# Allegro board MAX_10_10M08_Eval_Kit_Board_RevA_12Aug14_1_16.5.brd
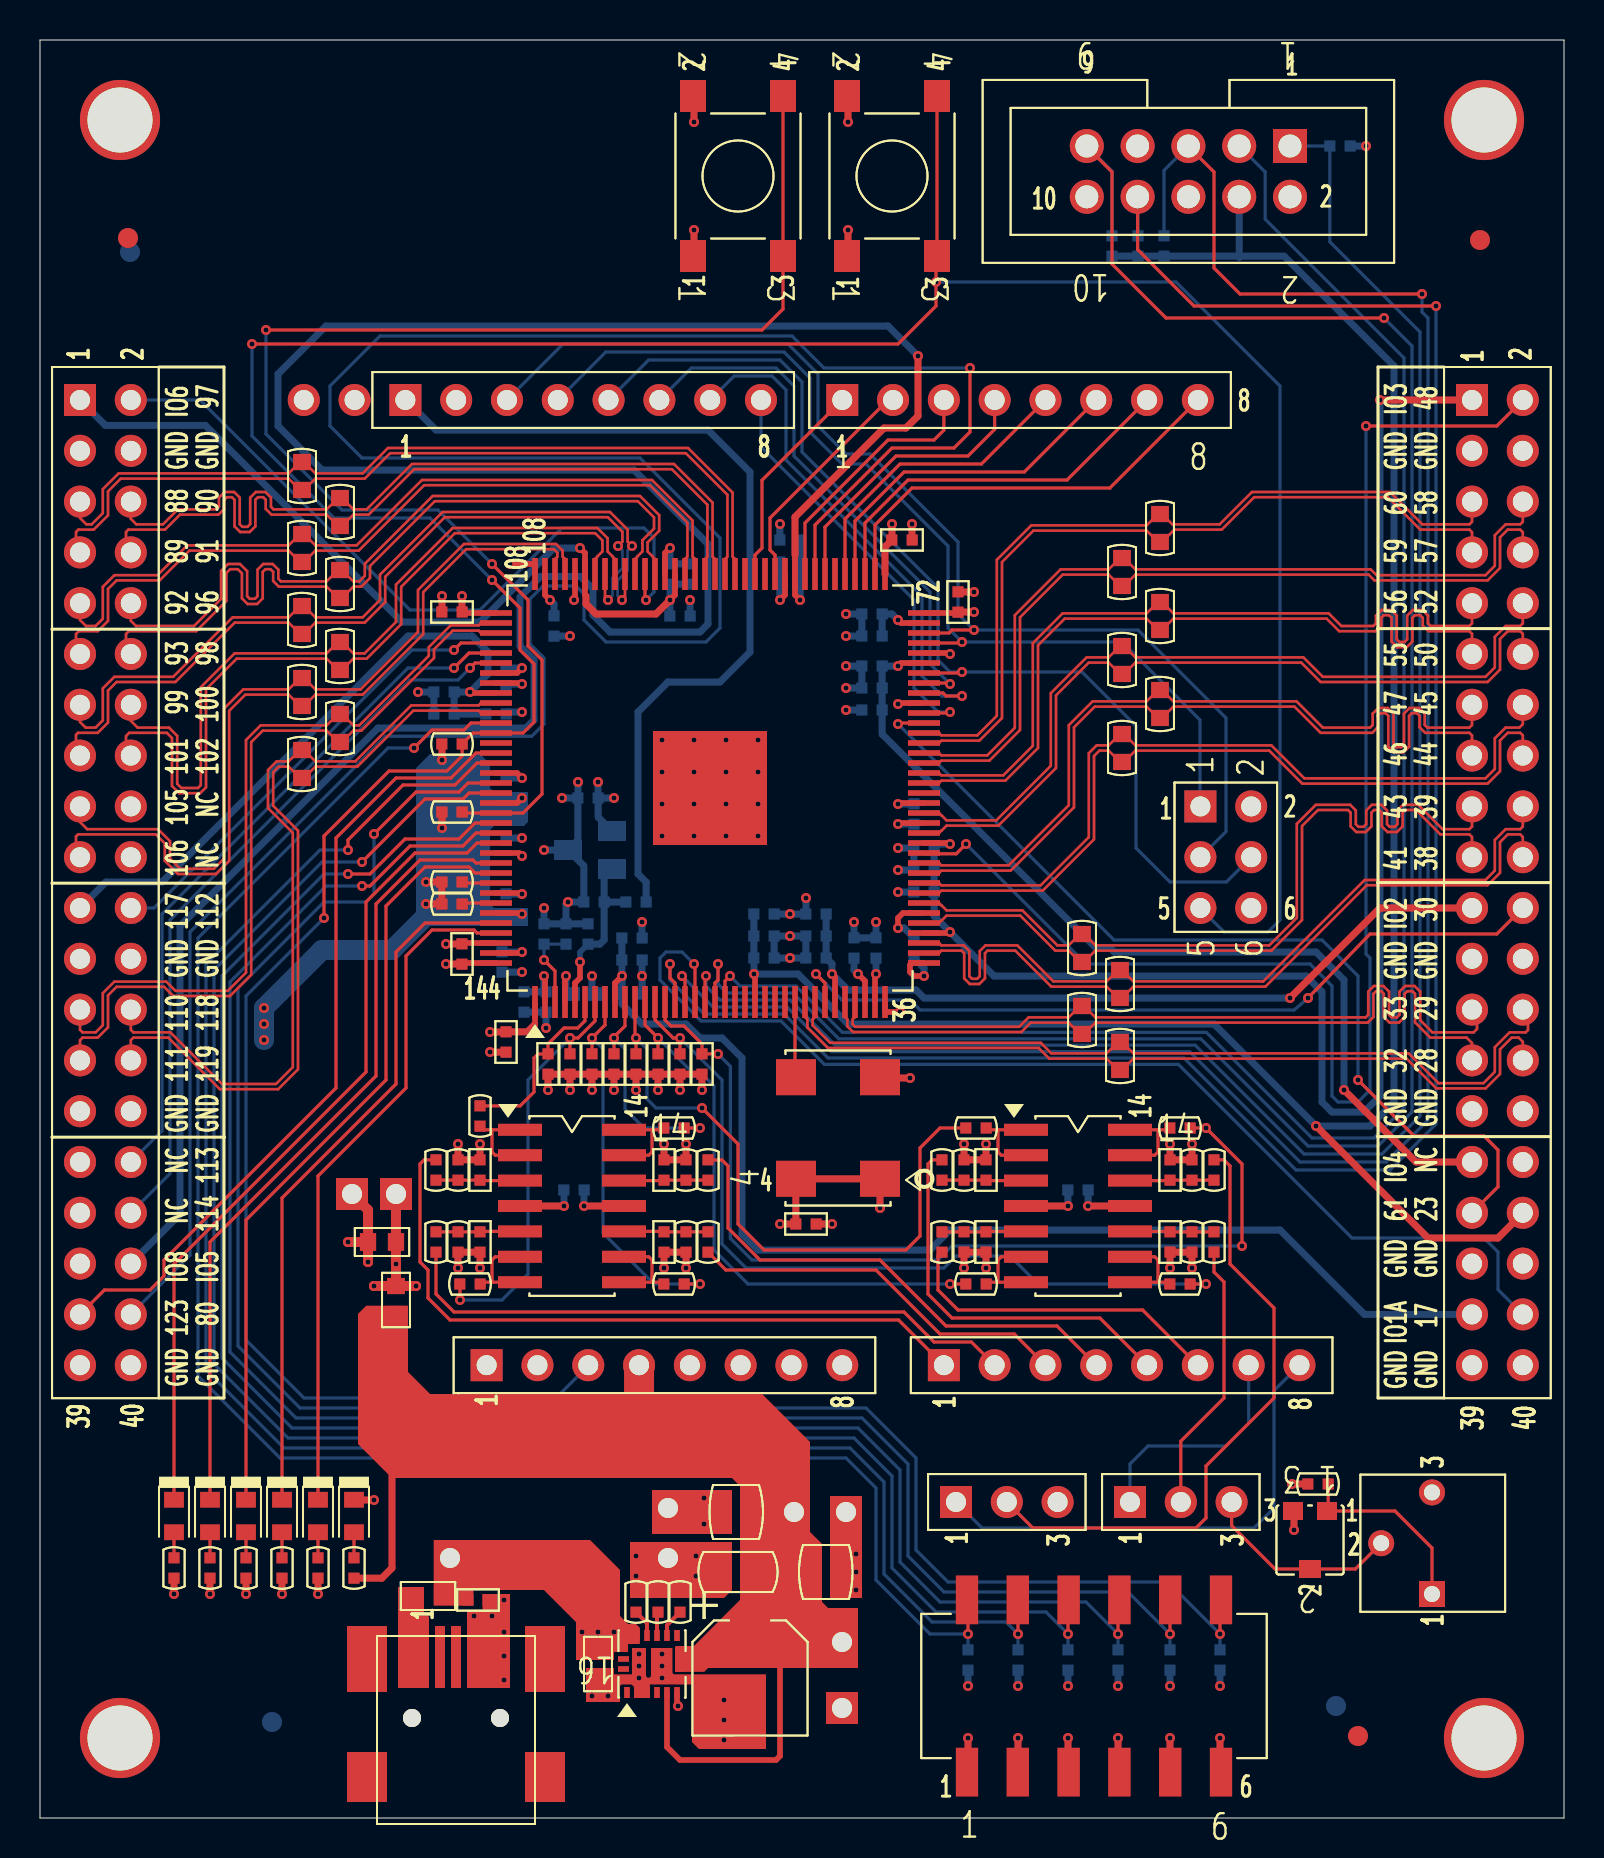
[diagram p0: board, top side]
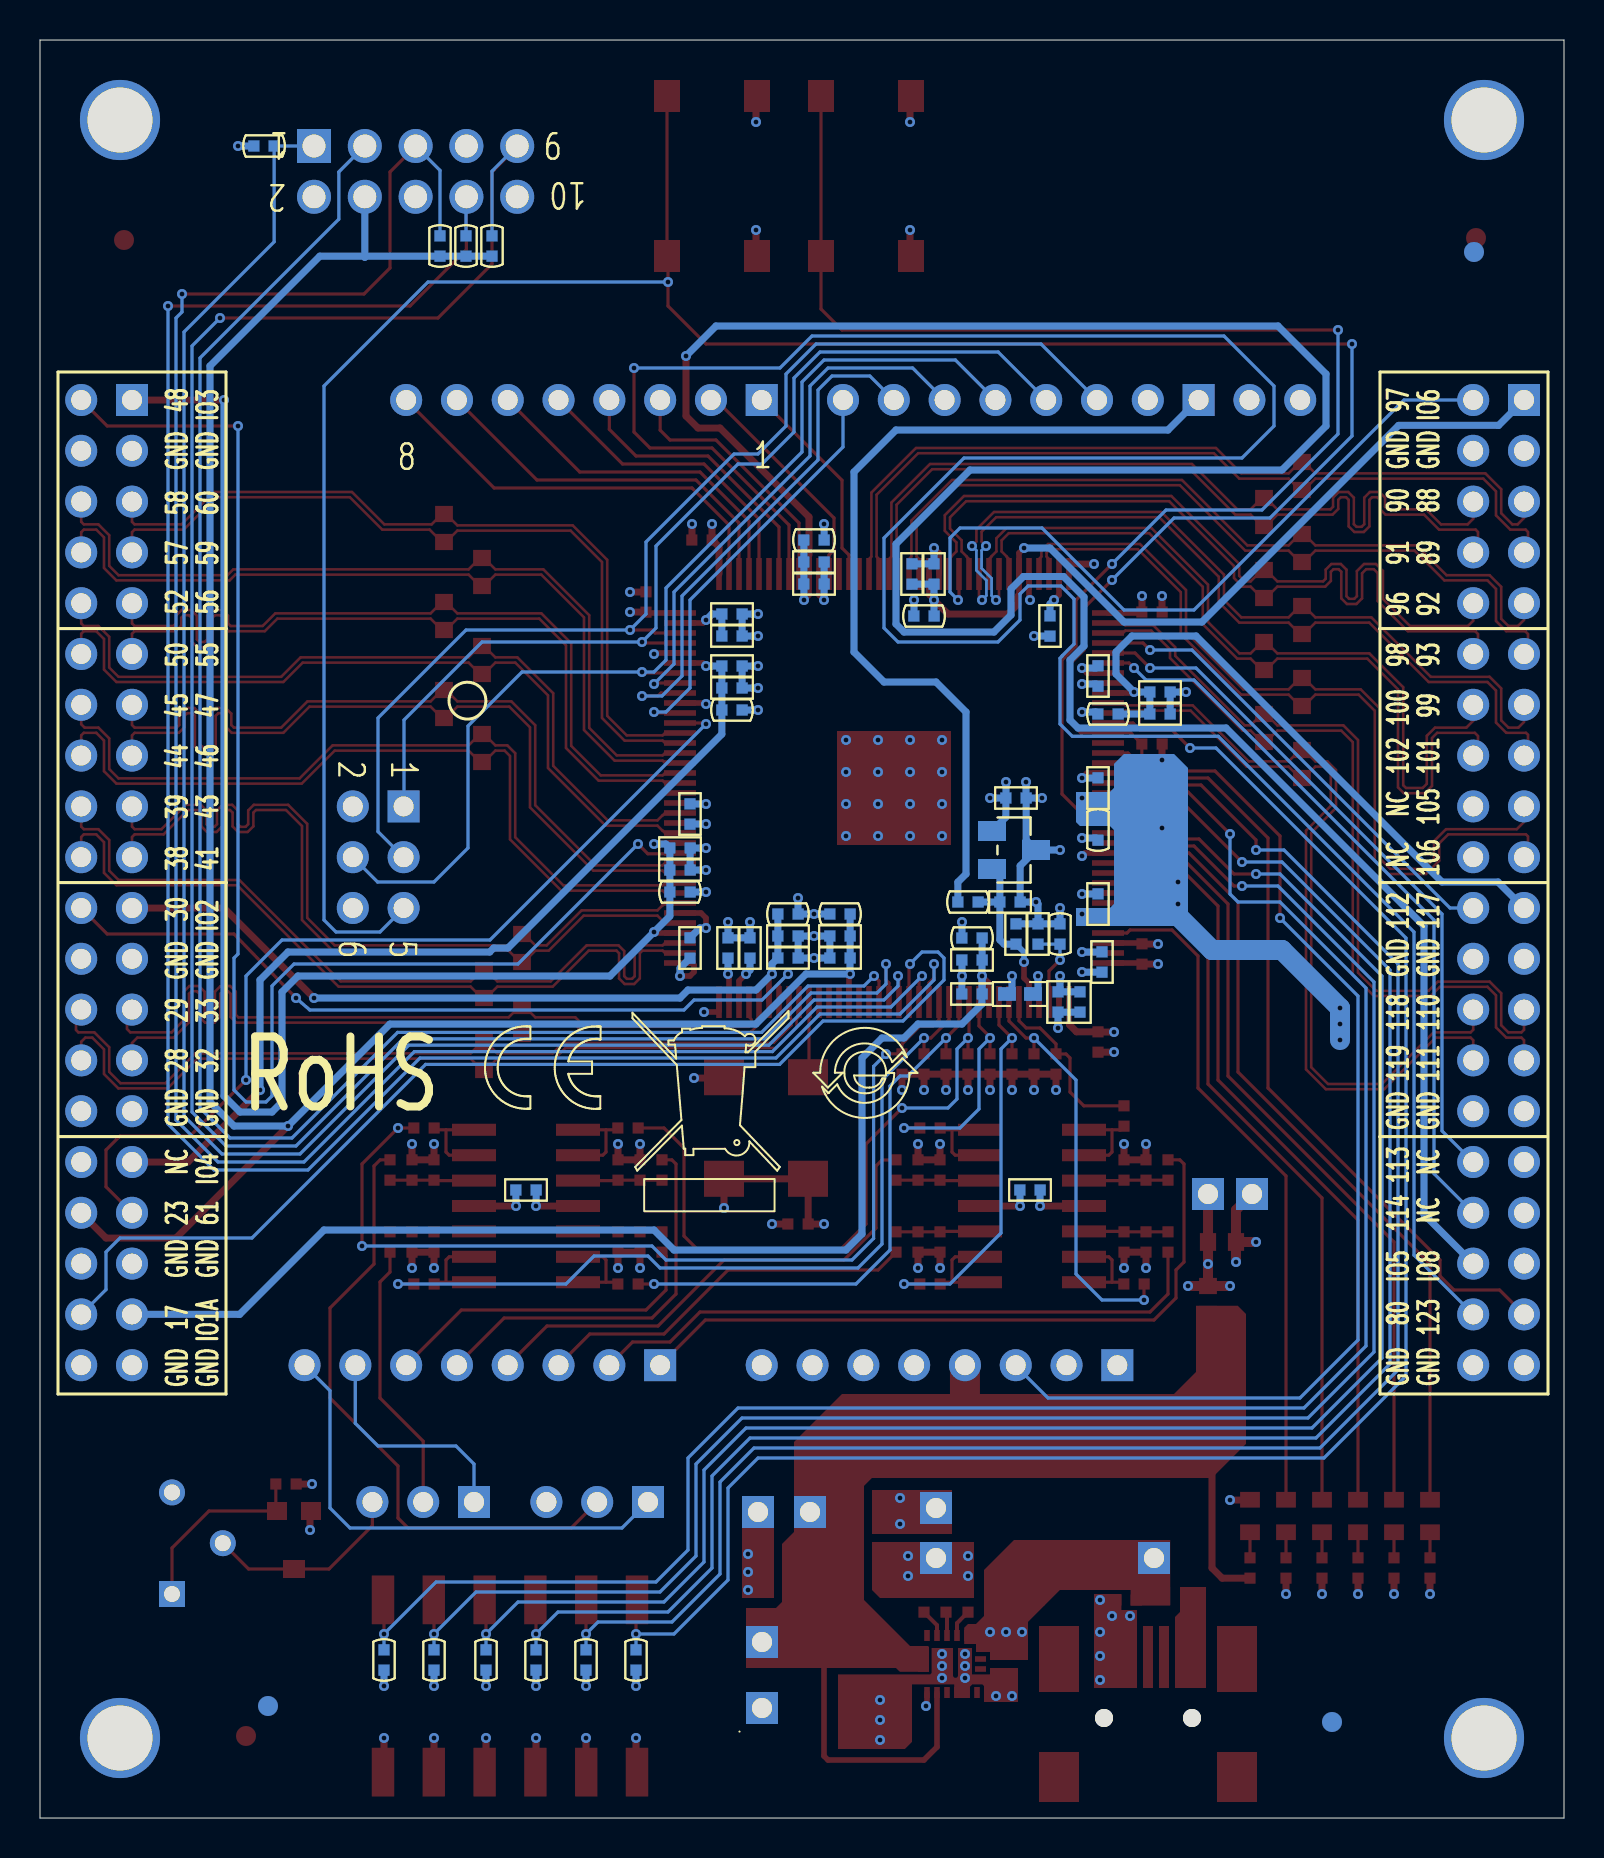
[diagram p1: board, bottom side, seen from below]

Outline 76.2 x 88.9 mm; copper layers: TOP, L2_GND, L3_PWR, BOTTOM. Coordinates in mm from the lower left corner of the outline.
Outline path: 0,88.9 0,0 76.2,0 76.2,88.9 0,88.9

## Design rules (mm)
net group DIFFIO_B1: nets DIFFIO_B1N DIFFIO_B1P
net group DIFFIO_B3: nets DIFFIO_B3N DIFFIO_B3P
net group DIFFIO_B5: nets DIFFIO_B5N DIFFIO_B5P
net group DIFFIO_B7: nets DIFFIO_B7N DIFFIO_B7P
net group DIFFIO_B9: nets DIFFIO_B9N DIFFIO_B9P
net group DIFFIO_B12: nets DIFFIO_B12N DIFFIO_B12P
net group DIFFIO_B14: nets DIFFIO_B14N DIFFIO_B14P
net group DIFFIO_B16: nets DIFFIO_B16N DIFFIO_B16P
net group DIFFIO_R18: nets DIFFIO_R18N DIFFIO_R18P
net group DIFFIO_R27: nets DIFFIO_R27N DIFFIO_R27P
net group DIFFIO_R28: nets DIFFIO_R28N DIFFIO_R28P
net group DIFFIO_R33: nets DIFFIO_R33N DIFFIO_R33P
net group DIFFIO_T1: nets DIFFIO_T1N DIFFIO_T1P
net group DIFFIO_T10: nets DIFFIO_T10N DIFFIO_T10P
net group DP1: nets DIFFIO_L20N/CLK1N DIFFIO_L20P/CLK1P
net group DP2: nets DIFFIO_L27N/PLL_CLKOUTN DIFFIO_L27P/PLL_CLKOUTP
net group DP3: nets DIFFIO_R14N/CLK2N DIFFIO_R14P/CLK2P
net group DP4: nets DIFFIO_R16N/CLK3N DIFFIO_R16P/CLK3P
net group DP5: nets DIFFIO_R26N/DPCLK2 DIFFIO_R26P/DPCLK3

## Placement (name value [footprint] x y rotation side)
C1  4.7uF  [CC0603]  27.9 7.7 270 top
C2  0.1uF  [CC0402]  21.9 10.9 180 top
C3  47uF/16V  [CAP_5P5_5P5_5P5]  35.5 7 180 top
C4  0.1uF  [CC0402]  25.3 40.8 90 bottom
C5  0.1uF  [CC0402]  40.7 43.5 270 bottom
C6  0.1uF  [CC0402]  25.7 59.6 90 bottom
C7  0.1uF  [CC0402]  41.8 43.5 270 bottom
C8  0.1uF  [CC0402]  43.7 43.5 270 bottom
C9  0.1uF  [CC0402]  21.1 43.2 270 top
C10  0.1uF  [CC0402]  23.3 57.1 90 bottom
C11  1uF  [CC0402]  43.1 63.9 180 top
C12  1uF  [CC0402]  27.4 44.2 270 bottom
C13  0.1uF  [CC0402]  23.3 38.8 90 top
C14  0.1uF  [CC0402]  20.6 60.3 0 top
C15  0.1uF  [CC0402]  45.9 60.8 270 top
C16  0.1uF  [CC0402]  43.7 50.2 270 bottom
C17  0.1uF  [CC0402]  29.6 41.2 180 bottom
C18  1uF  [CC0402]  29.6 42.9 180 bottom
C19  1nF  [CC0402]  22 28.8 270 top
C20  1nF  [CC0402]  31.2 32.4 90 top
C21  1nF  [CC0402]  31.2 28.8 270 top
C22  1nF  [CC0402]  22 32.4 90 top
C23  1nF  [CC0402]  47.3 28.8 270 top
C24  1nF  [CC0402]  56.5 32.4 90 top
C25  1nF  [CC0402]  47.3 32.4 90 top
C26  1nF  [CC0402]  56.5 28.8 270 top
C27  0.1uF  [CC0402]  41.6 57.6 0 bottom
C28  1uF  [CC0402]  41.6 56.5 0 bottom
C29  0.1uF  [CC0402]  37.5 61.7 0 bottom
C30  1uF  [CC0402]  37.5 62.8 0 bottom
C31  0.1uF  [CC0402]  38.8 43 0 bottom
C32  1uF  [CC0402]  38.8 44.1 0 bottom
C33  0.1uF  [CC0402]  44.2 48.5 0 bottom
C34  1uF  [CC0402]  44.2 47.4 0 bottom
C35  0.1uF  [CC0402]  38.3 29.7 180 top
C36  0.1uF  [CC0402]  31.5 62.2 270 bottom
C37  1uF  [CC0402]  32.6 62.2 270 bottom
C38  0.1uF  [CC0402]  20.2 56.3 0 bottom
C39  1uF  [CC0402]  20.2 55.2 0 bottom
C40  0.1uF  [CC0402]  23.3 45.7 270 bottom
C41  1uF  [CC0402]  23.3 51.5 270 bottom
C42  0.1uF  [CC0402]  36.2 43 180 bottom
C43  1uF  [CC0402]  36.2 44.1 180 bottom
C44  1uF  [CC0402]  24.2 40.8 90 bottom
C45  1uF  [CC0402]  41.6 59.1 0 bottom
C46  0.1uF  [CC0402]  26.3 44.2 270 bottom
C47  0.1uF  [CC0402]  27.4 51 0 bottom
C48  0.1uF  [CC0402]  23.1 42.8 90 bottom
C49  0.1uF  [CC0402]  41.6 60.2 0 bottom
C50  10uF  [CC0603]  17.1 28.8 180 top
C51  0.1uF  [CC0402]  26.7 31.4 180 bottom
C52  0.1uF  [CC0402]  51.9 31.4 180 bottom
C53  1nF  [CC0402]  25.4 37.7 270 top
C54  1nF  [CC0402]  26.5 37.7 270 top
C55  1nF  [CC0402]  27.6 37.7 270 top
C56  1nF  [CC0402]  28.7 37.7 270 top
C57  1nF  [CC0402]  29.8 37.7 270 top
C58  1nF  [CC0402]  30.9 37.7 270 top
C59  1nF  [CC0402]  32 37.7 270 top
C60  1nF  [CC0402]  33.1 37.7 270 top
C61  1uF  [CC0402]  27.7 45.8 0 bottom
D1  Red  [LED_0603]  6.7 15.1 90 top
D2  Red  [LED_0603]  8.5 15.1 90 top
D3  Red  [LED_0603]  10.3 15.1 90 top
D4  Red  [LED_0603]  12.1 15.1 90 top
D5  Red  [LED_0603]  13.9 15.1 90 top
D6  Green  [LED_0603]  15.7 15.1 90 top
J1  -  [SKT_MINIUSB_B_RA]  20.8 5 0 top
J2  PPTC081LFBN-RC  [SKT_SULLINS_PPTC_1X8_100]  22.33 22.64 0 top
J3  PPTC081LFBN-RC  [SKT_SULLINS_PPTC_1X8_100_ALT1]  18.27 70.9 0 top
J4  PPTC081LFBN-RC  [SKT_SULLINS_PPTC_1X8_100]  45.19 22.64 0 top
J5  PPTC081LFBN-RC  [SKT_SULLINS_PPTC_1X8_100]  40.11 70.9 0 top
J6  HEADER 3  [HDR_3M_961_1X3_100]  45.8 15.8 0 top
J7  HEADER 3  [HDR_3M_961_1X3_100]  54.5 15.8 0 top
J8  Header2x20  [SKT_SULLINS_PPPC_2X20_100]  71.6 70.9 270 top
J9  Header2x20  [SKT_SULLINS_PPPC_2X20_100]  2 70.9 270 top
J10  70246-1004  [HDR_MOLEX_70246_2X5_100]  62.5 83.6 180 top
J11  87227-3  [HDR_TE_87227_2X3_100]  58.02 50.58 0 top
L1  600ohm 500mA  [FB0603]  19.4 11.1 180 top
L2  600ohm 500mA  [FB0603]  17.8 25.9 90 top
L3  Ferrite Bead  [FB0402]  27.2 41.2 180 bottom
NOREF  -  [unnamed]  65.9 4.1 0 top
NOREF#2  -  [#2]  -5 -152.4 90 top
NOREF#3  -  [unnamed]  72 78.9 0 top
NOREF#4  -  [unnamed]  72.2 4 0 top
NOREF#5  -  [unnamed]  4 4 0 top
NOREF#6  -  [#2]  139.19 -79.15 0 top
NOREF#7  -  [#2]  -5 -152.5 0 top
NOREF#8  -  [#2]  0 0 90 top
NOREF#9  -  [unnamed]  4.4 79 0 top
NOREF#10  -  [#2]  231.1 -145.9 0 top
NOREF#11  -  [unnamed]  4 84.9 0 top
NOREF#12  -  [unnamed]  72.2 84.9 0 top
NOREF#13  -  [#2]  0 88.9 0 top
NOREF#14  -  [unnamed]  4.5 78.3 180 bottom
NOREF#15  -  [unnamed]  64.8 5.6 180 bottom
NOREF#16  -  [#2]  234.19 -137.57 180 bottom
NOREF#17  -  [unnamed]  11.6 4.8 180 bottom
R1  0.1  [CR0805W]  39.3 12.3 0 top
R2  1K  [CR0402]  15.7 12.5 270 top
R3  100  [CR0805]  34.9 12.3 0 top
R4  0.1  [CR0805W]  34.8 15.3 180 top
R6  0  [CR0402]  29.6 44 0 bottom
R7  316  [CR0402]  33.4 28.8 270 top
R8  316  [CR0402]  19.8 28.8 270 top
R9  316  [CR0402]  33.4 32.4 90 top
R10  316  [CR0402]  19.8 32.4 90 top
R15  1K  [CR0402]  63.9 16.7 180 top
R16  10K  [RV_MURATA_PVZ3A]  63.5 13.9 180 top
R17  316  [CR0402]  58.7 32.4 90 top
R18  316  [CR0402]  45.1 28.8 270 top
R19  316  [CR0402]  58.7 28.8 270 top
R20  316  [CR0402]  45.1 32.4 90 top
R25  0  [CR0402]  41.6 55.4 180 bottom
R26  0  [CR0402]  37.5 63.9 180 bottom
R27  0  [CR0402]  38.8 45.2 180 bottom
R29  100  [CR0603]  56 55.7 90 top
R30  100  [CR0603]  54 41.7 90 top
R31  100  [CR0603]  54 38.1 90 top
R32  100  [CR0603]  54.1 57.9 90 top
R33  100  [CR0603]  52.1 43.5 90 top
R34  100  [CR0603]  52.1 39.9 90 top
R35  100  [CR0603]  56 60.1 90 top
R36  100  [CR0603]  54.1 53.5 90 top
R37  100  [CR0603]  54.1 62.3 90 top
R38  0  [CR0402]  44.2 46.3 180 bottom
R39  100  [CR0603]  56 64.5 90 top
R40  0  [CR0402]  32 60.1 0 bottom
R41  100  [CR0603]  13.1 67.1 270 top
R42  100  [CR0603]  15 54.5 270 top
R43  100  [CR0603]  15 65.3 270 top
R44  100  [CR0603]  13.1 52.7 270 top
R45  100  [CR0603]  13.1 63.5 270 top
R46  100  [CR0603]  15 61.7 270 top
R47  0  [CR0402]  22.8 55.2 0 bottom
R48  100  [CR0603]  13.1 59.9 270 top
R49  100  [CR0603]  15 58.1 270 top
R50  100  [CR0603]  13.1 56.3 270 top
R51  1K  [CR0402]  20.6 46.8 180 top
R52  1K  [CR0402]  20.6 45.7 180 top
R53  1K  [CR0402]  20.6 50.3 180 top
R54  10K  [CR0402]  53.6 78.6 270 bottom
R55  10K  [CR0402]  56.2 78.6 270 bottom
R56  10K  [CR0402]  54.9 78.6 270 bottom
R57  1K  [CR0402]  6.7 12.5 90 top
R58  1K  [CR0402]  8.5 12.5 90 top
R59  1K  [CR0402]  10.3 12.5 90 top
R60  1K  [CR0402]  12.1 12.5 90 top
R61  1K  [CR0402]  13.9 12.5 90 top
R62  1K  [CR0402]  65 83.6 180 bottom
R63  0  [CR0402]  23.3 49.4 270 bottom
R64  1K  [CR0402]  59 7.9 90 bottom
R65  1K  [CR0402]  56.5 7.9 90 bottom
R66  1K  [CR0402]  53.9 7.9 90 bottom
R67  1K  [CR0402]  51.4 7.9 90 bottom
R68  1K  [CR0402]  48.9 7.9 90 bottom
R69  1K  [CR0402]  46.4 7.9 90 bottom
R70  0  [CR0402]  36.2 45.2 0 bottom
R72  1K  [CR0402]  20.6 53.7 0 top
R73  0  [CR0402]  25.2 44.2 270 bottom
R74  0  [CR0402]  29.8 45.8 180 bottom
R75  0  [CR0402]  29.8 10.8 270 top
R76  0  [CR0402]  30.9 10.8 270 top
R77  0  [CR0402]  32 10.8 270 top
R78  316  [CR0402]  20.9 32.4 90 top
R79  316  [CR0402]  20.9 28.8 270 top
R80  316  [CR0402]  32.3 28.8 270 top
R81  316  [CR0402]  32.3 32.4 90 top
R82  316  [CR0402]  46.2 32.4 90 top
R83  316  [CR0402]  46.2 28.8 270 top
R84  316  [CR0402]  57.6 28.8 270 top
R85  316  [CR0402]  57.6 32.4 90 top
R86  100  [CR0402]  22 35.1 90 top
R87  100  [CR0402]  21.5 26.7 180 top
R88  100  [CR0402]  31.7 26.7 0 top
R89  100  [CR0402]  31.7 34.5 0 top
R90  100  [CR0402]  46.8 34.5 0 top
R91  100  [CR0402]  46.8 26.7 0 top
R92  100  [CR0402]  57 26.7 180 top
R93  100  [CR0402]  57 34.5 180 top
R94  10K  [RV_BOURNS_3362P]  69.6 11.2 90 top
SW1  PTS645SM43SMTR92 LFS  [SW_SP_ST_CK_PTS645_SM]  42.6 82.1 270 top
SW2  PTS645SM43SMTR92 LFS  [SW_SP_ST_CK_PTS645_SM]  34.9 82.1 270 top
SW3  219-6LPST  [SW_SP_ST_CTS_219_GW]  52.7 6.6 0 top
TP1  -  [TP_S_40_63]  20.5 13 0 top
TP2  -  [TP_S_40_63]  37.7 15.3 0 top
TP3  -  [TP_S_40_63]  40.3 15.3 0 top
TP4  -  [TP_S_40_63]  40.1 8.8 0 top
TP5  -  [TP_S_40_63]  31.4 15.5 0 top
TP6  -  [TP_S_40_63]  17.8 31.2 90 top
TP7  -  [TP_S_40_63]  15.6 31.2 90 top
TP8  -  [TP_S_40_63]  40.1 5.5 0 top
TP9  -  [TP_S_40_63]  31.4 13 0 top
U1  EP5388QI  [QFN16_0P5_3P0X3P0_H1P1]  30.6 7.7 90 top
U2  MAX 10M08  [TQFP144_0P5_22P2X22P2_H1P6_EP]  33.5 51.5 90 top
U3  LM2902DR2  [SO14_50_244]  26.6 30.6 0 top
U4  LM2902DR2  [SO14_50_244]  51.9 30.6 0 top
U5  MCP1525  [SOT23_3P]  27.5 48.4 270 bottom
X1  CB3LV-3C-50M0000  [OSC_4P_CB3LV]  39.9 34.5 90 top

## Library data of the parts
C1 = CAP NP
C2 C4-C49 C51-C61 = C
C3 = EEE-1CA470WR
C50 = LMK107BJ106MALTD
D1-D5 = LED_0603_Red
D6 = LED_LTST-C190KGKT
J1 = skt_miniusb_b_ra
J2 = Arduino UNO Connector - 1_1
J3 = Arduino UNO Connector - 3_1
J4 = Arduino UNO Connector - 2_1
J5 = Arduino UNO Connector - 4_1
J6 = HEADER 3_1
J7 = HEADER 3_0
J8 J9 = header2x20_0
J10 = header2x5_ftsh
J11 = hdr2x3_87227
L1 L2 = FB0603
L3 = BEAD
R1 R4 = ERJ-3RSFR10V
R2 R3 R6-R10 R15 R17-R20 R25-R27 R38 R40 R47 R51-R56 R63 R70 R73-R85 = R
R16 = PVZ3A103C01R00
R29-R37 R39 R41-R46 R48-R50 = 100R_0603
R57-R62 R64-R69 R72 = 1k_0402
R86-R93 = RC0402FR-07100RL
R94 = 3362P-1-103TLF
SW1 SW2 = EVQP0_1
SW3 = SW DIP-6/SM_0
TP1-TP9 = TP_S_40_0
U1 = EP5388QI_0
U2 = MAX 10M08_27
U3 U4 = LM2902DR2_0
U5 = MCP1525
X1 = crystal_50MhZ

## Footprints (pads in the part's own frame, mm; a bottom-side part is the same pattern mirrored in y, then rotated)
CAP_5P5_5P5_5P5
  rect 1.6x2.8 smd: 1(0,-2.15) 2(0,2.15)
CC0402
  rect 0.559x0.559 smd: 1(-0.508,0) 2(0.508,0)
CC0603
  rect 0.813x0.889 smd: 1(-0.699,0) 2(0.699,0)
CR0402
  rect 0.559x0.559 smd: 1(-0.508,0) 2(0.508,0)
CR0603
  rect 0.813x0.889 smd: 1(-0.699,0) 2(0.699,0)
CR0805
  rect 1.295x1.499 smd: 1(-0.95,0) 2(0.95,0)
CR0805W
  rect 0.74x2.2 smd: 1(-0.62,0) 2(0.62,0)
FB0402
  rect 0.889x0.686 smd: 1(-0.65,0) 2(0.65,0)
FB0603
  rect 0.813x0.889 smd: 1(-0.699,0) 2(0.699,0)
HDR_3M_961_1X3_100
  rect 1.6x1.6 hole 1: 1(0,0)
  round 1.6 hole 1: 2(2.54,0) 3(5.08,0)
HDR_MOLEX_70246_2X5_100
  rect 1.7x1.7 hole 1.15: 1(0,0)
  round 1.7 hole 1.15: 2(0,2.54) 3(2.54,0) 4(2.54,2.54) 5(5.08,0) 6(5.08,2.54) 7(7.62,0) 8(7.62,2.54) 9(10.16,0) 10(10.16,2.54)
HDR_TE_87227_2X3_100
  rect 1.6x1.6 hole 1: 1(0,0)
  round 1.6 hole 1: 2(2.54,0) 3(0,-2.54) 4(2.54,-2.54) 5(0,-5.08) 6(2.54,-5.08)
LED_0603
  rect 0.787x0.991 smd: 1(-0.813,0) 2(0.813,0)
OSC_4P_CB3LV
  rect 1.8x2 smd: 1(-2.54,-2.1) 2(2.54,-2.1) 3(2.54,2.1) 4(-2.54,2.1)
QFN16_0P5_3P0X3P0_H1P1
  rect 0.55x0.28 smd: 1(-1.425,1.25) 2(-1.425,0.75) 3(-1.425,0.25) 4(-1.425,-0.25) 5(-1.425,-0.75) 6(-1.425,-1.25) 9(1.425,-1.25) 10(1.425,-0.75) 11(1.425,-0.25) 12(1.425,0.25) 13(1.425,0.75) 14(1.425,1.25)
  rect 0.28x0.55 smd: 7(-0.25,-1.425) 8(0.25,-1.425) 15(0.25,1.425) 16(-0.25,1.425)
RV_BOURNS_3362P
  rect 1.3x1.3 hole 0.8: 1(0,0)
  round 1.3 hole 0.8: 2(2.54,2.54) 3(5.08,0)
RV_MURATA_PVZ3A
  rect 1x0.9 smd: 1(-0.85,-1.45) 3(0.85,-1.45)
  rect 1.1x0.9 smd: 2(0,1.45)
SKT_MINIUSB_B_RA
  rect 2x3.3 smd: (-4.45,2.95) (4.45,2.95)
  rect 2x2.5 smd: (-4.45,-2.95) (4.45,-2.95)
  round 0.9 hole 0.9 unplated: (-2.2,0) (2.2,0)
  rect 0.5x3.1 smd: 1(-1.6,3.05) 2(-0.8,3.05) 3(0,3.05) 4(0.8,3.05) 5(1.6,3.05)
SKT_SULLINS_PPPC_2X20_100
  rect 1.6x1.6 hole 1: 1(0,0)
  round 1.6 hole 1: 2(0,2.54) 3(2.54,0) 4(2.54,2.54) 5(5.08,0) 6(5.08,2.54) 7(7.62,0) 8(7.62,2.54) 9(10.16,0) 10(10.16,2.54) 11(12.7,0) 12(12.7,2.54) 13(15.24,0) 14(15.24,2.54) 15(17.78,0) 16(17.78,2.54) 17(20.32,0) 18(20.32,2.54) 19(22.86,0) 20(22.86,2.54) 21(25.4,0) 22(25.4,2.54) 23(27.94,0) 24(27.94,2.54) 25(30.48,0) 26(30.48,2.54) 27(33.02,0) 28(33.02,2.54) 29(35.56,0) 30(35.56,2.54) 31(38.1,0) 32(38.1,2.54) 33(40.64,0) 34(40.64,2.54) 35(43.18,0) 36(43.18,2.54) 37(45.72,0) 38(45.72,2.54) 39(48.26,0) 40(48.26,2.54)
SKT_SULLINS_PPTC_1X8_100
  rect 1.6x1.6 hole 1: 1(0,0)
  round 1.6 hole 1: 2(2.54,0) 3(5.08,0) 4(7.62,0) 5(10.16,0) 6(12.7,0) 7(15.24,0) 8(17.78,0)
SKT_SULLINS_PPTC_1X8_100_ALT1
  round 1.6 hole 1: (-5.08,0) (-2.54,0) 2(2.54,0) 3(5.08,0) 4(7.62,0) 5(10.16,0) 6(12.7,0) 7(15.24,0) 8(17.78,0)
  rect 1.6x1.6 hole 1: 1(0,0)
SO14_50_244
  rect 2.2x0.6 smd: 1(-2.6,3.81) 2(-2.6,2.54) 3(-2.6,1.27) 4(-2.6,0) 5(-2.6,-1.27) 6(-2.6,-2.54) 7(-2.6,-3.81) 8(2.6,-3.81) 9(2.6,-2.54) 10(2.6,-1.27) 11(2.6,0) 12(2.6,1.27) 13(2.6,2.54) 14(2.6,3.81)
SOT23_3P
  rect 1x1.4 smd: 1(-0.95,-1.1) 2(0.95,-1.1) 3(0,1.1)
SW_SP_ST_CK_PTS645_SM
  rect 1.6x1.3 smd: 1(4,-2.25) 2(-4,-2.25) 3(4,2.25) 4(-4,2.25)
SW_SP_ST_CTS_219_GW
  rect 1.118x2.438 smd: 1(-6.35,-4.305) 2(-3.81,-4.305) 3(-1.27,-4.305) 4(1.27,-4.305) 5(3.81,-4.305) 6(6.35,-4.305) 7(6.35,4.305) 8(3.81,4.305) 9(1.27,4.305) 10(-1.27,4.305) 11(-3.81,4.305) 12(-6.35,4.305)
TP_S_40_63
  rect 1.6x1.6 hole 1: 1(0,0)
TQFP144_0P5_22P2X22P2_H1P6_EP
  rect 1.6x0.28 smd: 1(-10.7,8.75) 2(-10.7,8.25) 3(-10.7,7.75) 4(-10.7,7.25) 5(-10.7,6.75) 6(-10.7,6.25) 7(-10.7,5.75) 8(-10.7,5.25) 9(-10.7,4.75) 10(-10.7,4.25) 11(-10.7,3.75) 12(-10.7,3.25) 13(-10.7,2.75) 14(-10.7,2.25) 15(-10.7,1.75) 16(-10.7,1.25) 17(-10.7,0.75) 18(-10.7,0.25) 19(-10.7,-0.25) 20(-10.7,-0.75) 21(-10.7,-1.25) 22(-10.7,-1.75) 23(-10.7,-2.25) 24(-10.7,-2.75) 25(-10.7,-3.25) 26(-10.7,-3.75) 27(-10.7,-4.25) 28(-10.7,-4.75) 29(-10.7,-5.25) 30(-10.7,-5.75) 31(-10.7,-6.25) 32(-10.7,-6.75) 33(-10.7,-7.25) 34(-10.7,-7.75) 35(-10.7,-8.25) 36(-10.7,-8.75) 73(10.7,-8.75) 74(10.7,-8.25) 75(10.7,-7.75) 76(10.7,-7.25) 77(10.7,-6.75) 78(10.7,-6.25) 79(10.7,-5.75) 80(10.7,-5.25) 81(10.7,-4.75) 82(10.7,-4.25) 83(10.7,-3.75) 84(10.7,-3.25) 85(10.7,-2.75) 86(10.7,-2.25) 87(10.7,-1.75) 88(10.7,-1.25) 89(10.7,-0.75) 90(10.7,-0.25) 91(10.7,0.25) 92(10.7,0.75) 93(10.7,1.25) 94(10.7,1.75) 95(10.7,2.25) 96(10.7,2.75) 97(10.7,3.25) 98(10.7,3.75) 99(10.7,4.25) 100(10.7,4.75) 101(10.7,5.25) 102(10.7,5.75) 103(10.7,6.25) 104(10.7,6.75) 105(10.7,7.25) 106(10.7,7.75) 107(10.7,8.25) 108(10.7,8.75)
  rect 0.28x1.6 smd: 37(-8.75,-10.7) 38(-8.25,-10.7) 39(-7.75,-10.7) 40(-7.25,-10.7) 41(-6.75,-10.7) 42(-6.25,-10.7) 43(-5.75,-10.7) 44(-5.25,-10.7) 45(-4.75,-10.7) 46(-4.25,-10.7) 47(-3.75,-10.7) 48(-3.25,-10.7) 49(-2.75,-10.7) 50(-2.25,-10.7) 51(-1.75,-10.7) 52(-1.25,-10.7) 53(-0.75,-10.7) 54(-0.25,-10.7) 55(0.25,-10.7) 56(0.75,-10.7) 57(1.25,-10.7) 58(1.75,-10.7) 59(2.25,-10.7) 60(2.75,-10.7) 61(3.25,-10.7) 62(3.75,-10.7) 63(4.25,-10.7) 64(4.75,-10.7) 65(5.25,-10.7) 66(5.75,-10.7) 67(6.25,-10.7) 68(6.75,-10.7) 69(7.25,-10.7) 70(7.75,-10.7) 71(8.25,-10.7) 72(8.75,-10.7) 109(8.75,10.7) 110(8.25,10.7) 111(7.75,10.7) 112(7.25,10.7) 113(6.75,10.7) 114(6.25,10.7) 115(5.75,10.7) 116(5.25,10.7) 117(4.75,10.7) 118(4.25,10.7) 119(3.75,10.7) 120(3.25,10.7) 121(2.75,10.7) 122(2.25,10.7) 123(1.75,10.7) 124(1.25,10.7) 125(0.75,10.7) 126(0.25,10.7) 127(-0.25,10.7) 128(-0.75,10.7) 129(-1.25,10.7) 130(-1.75,10.7) 131(-2.25,10.7) 132(-2.75,10.7) 133(-3.25,10.7) 134(-3.75,10.7) 135(-4.25,10.7) 136(-4.75,10.7) 137(-5.25,10.7) 138(-5.75,10.7) 139(-6.25,10.7) 140(-6.75,10.7) 141(-7.25,10.7) 142(-7.75,10.7) 143(-8.25,10.7) 144(-8.75,10.7)
  rect 5.7x5.7 smd: 145(0,0)
unnamed
  round 1 smd: (0,0)

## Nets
3.3V: C3.1 J2.4(VCC3P3) L2.1 R1.1 R2.2 R3.2 R4.1 TP2.1(TP) TP4.1(TP) U1.5(VSENSE) U1.7(VOUT1) U1.8(VOUT2)
AGND: C4.1 C5.1 C6.1 C7.1 C12.1 C17.1 C18.1 C19.2 C20.2 C21.2 C22.2 C23.2 C24.2 C25.2 C26.2 C44.1 C45.1 C46.1 C47.1 C48.1 C49.1 C50.2 C51.1 C52.1 C53.2 C54.2 C55.2 C56.2 C57.2 C58.2 C59.2 C60.2 C61.1 J3.2(GND) J6.3 L3.1 R16.3 R73.1 R78.2 R79.2 R80.2 R81.2 R82.2 R83.2 R84.2 R85.2 R94.3 TP7.1(TP) U3.11(GND) U4.11(GND) U5.3(VSS)
DGND: C1.2 C2.1 C3.2 C8.1 C9.1 C10.1 C11.1 C13.1 C14.1 C15.1 C16.1 C27.1 C28.1 C29.1 C30.1 C31.1 C32.1 C33.1 C34.1 C35.1 C36.1 C37.1 C38.1 C39.1 C40.1 C41.1 C42.1 C43.1 D6.2(CATHODE) J1.4(ID) J1.5(GND) J2.6(GND1) J2.7(GND2) J8.3 J8.4 J8.23 J8.24 J8.29 J8.30 J8.35 J8.36 J8.39 J8.40 J9.3 J9.4 J9.23 J9.24 J9.29 J9.30 J9.39 J9.40 J10.2 J10.10 J11.6 R3.1 R62.1 R75.1 R76.1 R77.1 SW1.1(A1) SW1.2(A2) SW2.1(A1) SW2.2(A2) SW3.1(A1) SW3.2(A2) SW3.3(A3) SW3.4(A4) SW3.5(A5) SW3.6(A6) TP8.1(TP) TP9.1(TP) U1.2(PGND1) U1.3(PGND2) U1.6(AGND) U2.42(GND1) U2.53(GND2) U2.63(GND3) U2.68(GND4) U2.83(GND5) U2.95(GND6) U2.104(GND7) U2.116(GND8) U2.125(GND9) U2.133(GND10) U2.137(GND11) U2.142(GND12) U2.145(PAD) X1.2(GND)
VBUS_5V: C1.1 C2.2 J2.5(VCC5) J11.2 L1.1 TP1.1(TP) U1.13(ENABLE) U1.14(VIN)
VCC_CORE: C8.2 C9.2 C10.2 C11.2 C13.2 C14.2 C15.2 C16.2 C35.2 R1.2 TP3.1(TP) U2.1(VCC_ONE10) U2.36(VCC_ONE5) U2.37(VCC_ONE4) U2.51(VCC_ONE3) U2.72(VCC_ONE2) U2.73(VCC_ONE1) U2.108(VCC_ONE9) U2.109(VCC_ONE8) U2.115(VCC_ONE7) U2.144(VCC_ONE6) X1.1(EN) X1.4(VCC)
VCC_IO: J2.2(IOREF) R4.2 R25.2 R26.2 R27.2 R38.2 R40.2 R47.2 R63.2 R70.2 TP5.1(TP)
VCC_IO1A: C17.2 C18.2 J8.37 R6.1 U2.9(VCCIO1A)
VCC_IO1B: C42.2 C43.2 J8.34 J10.4 R54.2 R55.2 R56.2 R70.1 U2.23(VCCIO1B)
VCC_IO2: C31.2 C32.2 J8.21 R27.1 U2.31(VCCIO2)
VCC_IO3: C33.2 C34.2 J8.1 R38.1 U2.40(VCCIO3_1) U2.49(VCCIO3_2)
VCC_IO4: C27.2 C28.2 J8.31 R25.1 U2.67(VCCIO4)
VCC_IO5: C29.2 C30.2 J9.36 R26.1 U2.82(VCCIO5)
VCC_IO6: C36.2 C37.2 J9.1 R40.1 U2.94(VCCIO6_1) U2.103(VCCIO6_2)
VCC_IO7: C38.2 C39.2 J9.21 R47.1 U2.117(VCCIO7)
VCC_IO8: C40.2 C41.2 J9.35 R51.2 R52.2 R53.2 R57.1 R58.1 R59.1 R60.1 R61.1 R63.1 R64.1 R65.1 R66.1 R67.1 R68.1 R69.1 R72.1 U2.128(VCCIO8_2) U2.139(VCCIO8_1)
VCCA_3.3V: C4.2 C5.2 C6.2 C7.2 C44.2 C45.2 C47.2 C48.2 C49.2 C50.1 C51.2 C52.2 L2.2 R6.2 R15.2 TP6.1(TP) U2.2(VCCA6) U2.34(VCCA2) U2.35(VCCA1) U2.71(VCCA5) U2.107(VCCA3) U2.143(VCCA4) U3.4(VCC) U4.4(VCC) U5.1(VIN)
ADC1IN1: R86.1 U3.1(1OUT) U3.2(1IN-)
ADC1IN2: R87.1 U3.6(2IN-) U3.7(2OUT)
ADC1IN3: R88.1 U3.8(3OUT) U3.9(3IN-)
ADC1IN4: R89.1 U3.13(4IN-) U3.14(4OUT)
ADC1IN5: R90.2 U4.1(1OUT) U4.2(1IN-)
ADC1IN6: R91.2 U4.6(2IN-) U4.7(2OUT)
ADC1IN7: R92.2 U4.8(3OUT) U4.9(3IN-)
ADC1IN8: R93.2 U4.13(4IN-) U4.14(4OUT)
ARDUINO_A0: J4.1(ANALOG_IN0) R10.2
ARDUINO_A1: J4.2(ANALOG_IN1) R8.2
ARDUINO_A2: J4.3(ANALOG_IN2) R7.2
ARDUINO_A3: J4.4(ANALOG_IN3) R9.2
ARDUINO_A4: J4.5(ANALOG_IN4) R20.2
ARDUINO_A5: J4.6(ANALOG_IN5) R18.2
ARDUINO_A6: J4.7(ANALOG_IN6) J7.1
ARDUINO_A7: J4.8(ANALOG_IN7) J6.1
ARDUINO_IO0: J5.8(ARDUINO_IO0) U2.74(DIFFIO_RX_R2P)
ARDUINO_IO1: J5.7(ARDUINO_IO1) U2.75(DIFFIO_RX_R1P)
ARDUINO_IO2: J5.6(ARDUINO_IO2) U2.76(DIFFIO_RX_R2N)
ARDUINO_IO3: J5.5(ARDUINO_IO3) U2.77(DIFFIO_RX_R1N)
ARDUINO_IO4: J5.4(ARDUINO_IO4) U2.79(DIFFIO_RX_R7P)
ARDUINO_IO5: J5.3(ARDUINO_IO5) U2.81(DIFFIO_RX_R7N)
ARDUINO_IO6: J5.2(ARDUINO_IO6) U2.84(DIFFIO_RX_R11P)
ARDUINO_IO7: J5.1(ARDUINO_IO7) U2.86(DIFFIO_RX_R11N)
ARDUINO_IO8: J3.8(ARDUINO_IO8) U2.62(DIFFIO_TX_RX_B20P)
ARDUINO_IO9: J3.7(ARDUINO_IO9) U2.64(DIFFIO_TX_RX_B23N)
ARDUINO_IO10: J3.6(ARDUINO_IO10) U2.65(DIFFIO_TX_RX_B23P)
ARDUINO_IO11: J3.5(ARDUINO_IO11) J11.4 U2.66(DIFFIO_TX_RX_B25N)
ARDUINO_IO12: J3.4(ARDUINO_IO12) J11.1 U2.69(DIFFIO_TX_RX_B27N)
ARDUINO_IO13: J3.3(ARDUINO_IO13) J11.3 U2.70(DIFFIO_TX_RX_B27P)
ARDUINO_VREF: J3.1(ANALOG_VREF) R74.1
BOOT_SEL: R64.2 SW3.7(B6) U2.126(BOOT_SEL)
DIFFIO_B1N: J8.20 R30.1 U2.38(DIFFIO_TX_RX_B1N)
DIFFIO_B1P: J8.18 R30.2 U2.39(DIFFIO_TX_RX_B1P)
DIFFIO_B3N: J8.19 R33.1 U2.41(DIFFIO_TX_RX_B3N)
DIFFIO_B3P: J8.17 R33.2 U2.43(DIFFIO_TX_RX_B3P)
DIFFIO_B5N: J8.16 R36.1 U2.44(DIFFIO_TX_RX_B5N)
DIFFIO_B5P: J8.14 R36.2 U2.45(DIFFIO_TX_RX_B5P)
DIFFIO_B7N: J8.15 R29.1 U2.46(DIFFIO_TX_RX_B7N)
DIFFIO_B7P: J8.13 R29.2 U2.47(DIFFIO_TX_RX_B7P)
DIFFIO_B9N: J8.12 R32.1 U2.50(DIFFIO_TX_RX_B9N)
DIFFIO_B9P: J8.10 R32.2 U2.52(DIFFIO_TX_RX_B9P)
DIFFIO_B12N: J8.11 R35.1 U2.55(DIFFIO_TX_RX_B12N)
DIFFIO_B12P: J8.9 R35.2 U2.56(DIFFIO_TX_RX_B12P)
DIFFIO_B14N: J8.8 R37.1 U2.57(DIFFIO_TX_RX_B14N)
DIFFIO_B14P: J8.6 R37.2 U2.58(DIFFIO_TX_RX_B14P)
DIFFIO_B16N: J8.7 R39.1 U2.59(DIFFIO_TX_RX_B16N)
DIFFIO_B16P: J8.5 R39.2 U2.60(DIFFIO_TX_RX_B16P)
DIFFIO_L20N/CLK1N: J8.28 R31.1 U2.28(DIFFIO_RX_L20N/CLK1N)
DIFFIO_L20P/CLK1P: J8.26 R31.2 U2.29(DIFFIO_RX_L20P/CLK1P)
DIFFIO_L27N/PLL_CLKOUTN: J8.27 R34.1 U2.32(DIFFIO_RX_L27N/PLL_L_CLKOUTN)
DIFFIO_L27P/PLL_CLKOUTP: J8.25 R34.2 U2.33(DIFFIO_RX_L27P/PLL_L_CLKOUTP)
DIFFIO_R14N/CLK2N: J9.7 R41.2 U2.89(DIFFIO_RX_R14N/CLK2N)
DIFFIO_R14P/CLK2P: J9.5 R41.1 U2.88(DIFFIO_RX_R14P/CLK2P)
DIFFIO_R16N/CLK3N: J9.8 R43.2 U2.91(DIFFIO_RX_R16N/CLK3N)
DIFFIO_R16P/CLK3P: J9.6 R43.1 U2.90(DIFFIO_RX_R16P/CLK3P)
DIFFIO_R18N: J9.11 R45.2 U2.93(DIFFIO_RX_R18N)
DIFFIO_R18P: J9.9 R45.1 U2.92(DIFFIO_RX_R18P)
DIFFIO_R26N/DPCLK2: J9.12 R46.2 U2.98(DIFFIO_RX_R26N/DPCLK2)
DIFFIO_R26P/DPCLK3: J9.10 R46.1 U2.96(DIFFIO_RX_R26P/DPCLK3)
DIFFIO_R27N: J9.15 R48.2 U2.101(DIFFIO_RX_R27N)
DIFFIO_R27P: J9.13 R48.1 U2.99(DIFFIO_RX_R27P)
DIFFIO_R28N: J9.16 R49.2 U2.102(DIFFIO_RX_R28N)
DIFFIO_R28P: J9.14 R49.1 U2.100(DIFFIO_RX_R28P)
DIFFIO_R33N: J9.19 R50.2 U2.106(DIFFIO_RX_R33N)
DIFFIO_R33P: J9.17 R50.1 U2.105(DIFFIO_RX_R33P)
DIFFIO_T1N: J9.27 R42.2 U2.111(DIFFIO_RX_T1N)
DIFFIO_T1P: J9.25 R42.1 U2.110(DIFFIO_RX_T1P)
DIFFIO_T4N: J9.32 U2.113(DIFFIO_RX_T4N)
DIFFIO_T6P: J9.34 U2.114(DIFFIO_RX_T6P)
DIFFIO_T10N: J9.28 R44.2 U2.119(DIFFIO_RX_T10N)
DIFFIO_T10P: J9.26 R44.1 U2.118(DIFFIO_RX_T10P)
JTAGEN: J10.8 R56.1 U2.15(DIFFIO_RX_L9P/JTAGEN)
LED1: D1.2(CATHODE) U2.132(DIFFIO_RX_T22P)
LED2: D2.2(CATHODE) U2.134(DIFFIO_RX_T22N/CRC_ERROR)
LED3: D3.2(CATHODE) U2.135(DIFFIO_RX_T23N)
LED4: D4.2(CATHODE) U2.140(DIFFIO_RX_T26P)
LED5: D5.2(CATHODE) U2.141(DIFFIO_RX_T26N)
NCONFIG: R53.1 SW2.3(B1) SW2.4(B2) U2.129(NCONFIG)
OSC_OUT: U2.27(DIFFIO_RX_L18P/CLK0P) X1.3(OUTPUT)
RESET_N: J2.3(ARDUINO_RESET_N) J11.5 R72.2 SW1.3(B1) SW1.4(B2) U2.121(DIFFIO_RX_T16N/DEV_CLRN)
SWITCH 1: R69.2 SW3.12(B1) U2.120(DIFFIO_RX_T16P)
SWITCH 2: R68.2 SW3.11(B2) U2.124(DIFFIO_RX_T19P)
SWITCH 3: R67.2 SW3.10(B3) U2.127(DIFFIO_RX_T19N)
SWITCH 4: R66.2 SW3.9(B4) U2.130(DIFFIO_RX_T20P)
SWITCH 5: R65.2 SW3.8(B5) U2.131(DIFFIO_RX_T20N)
TCK: J10.1 R62.2 U2.18(DIFFIO_RX_L11P/TCK)
TDI: J10.9 R54.1 U2.19(DIFFIO_RX_L12N/TDI)
TDO: J10.3 U2.20(DIFFIO_RX_L12P/TDO)
TMS: J10.5 R55.1 U2.16(DIFFIO_RX_L11N/TMS)
VREF_2.5V: C12.2 C61.2 R74.2 U2.5(ADC_VREF) U5.2(VOUT)
VREFB1N0: J8.38 U2.17(VREFB1N0)
VREFB2N0: J8.22 U2.30(VREFB2N0)
VREFB3N0: J8.2 U2.48(VREFB3N0)
VREFB4N0: J8.33 U2.61(VREFB4N0)
VREFB5N0: J9.38 U2.80(VREFB5N0)
VREFB6N0: J9.2 U2.97(VREFB6N0)
VREFB7N0: J9.22 U2.112(VREFB7N0)
VREFB8N0: J9.37 U2.123(VREFB8N0)
N15317190: R75.2 U1.12(VS0)
N15317205: R76.2 U1.11(VS1)
N15317224: R77.2 U1.10(VS2)
N15317661: J1.1(VCC) L1.2
N16795142: J6.2 R17.2
N16798349: J7.2 R19.2
N16798444: J7.3 R16.2 R94.2
N16825621: R51.1 U2.136(DIFFIO_RX_T24P/NSTATUS)
N16825626: R52.1 U2.138(DIFFIO_RX_T24N/CONF_DONE)
N16827450: D1.1(ANODE) R57.2
N16827455: D2.1(ANODE) R58.2
N16827460: D3.1(ANODE) R59.2
N16827465: D4.1(ANODE) R60.2
N16856284: D5.1(ANODE) R61.2
N16879493: C22.1 R10.1 R78.1 U3.3(1IN+)
N16880012: C19.1 R8.1 R79.1 U3.5(2IN+)
N16880301: C21.1 R7.1 R80.1 U3.10(3IN+)
N16880631: C20.1 R9.1 R81.1 U3.12(4IN+)
N16880930: C25.1 R20.1 R82.1 U4.3(1IN+)
N16881114: C23.1 R18.1 R83.1 U4.5(2IN+)
N16881411: C26.1 R19.1 R84.1 U4.10(3IN+)
N16881659: C24.1 R17.1 R85.1 U4.12(4IN+)
N16906288: C46.2 R73.2 U2.3(ANAIN1)
N16996005: C53.1 R86.2 U2.6(DIFFIO_RX_L1N/ADC1IN1)
N16998422: C54.1 R87.2 U2.7(DIFFIO_RX_L1P/ADC1IN2)
N16998544: C55.1 R88.2 U2.8(DIFFIO_RX_L3N/ADC1IN3)
N16998676: C56.1 R89.2 U2.10(DIFFIO_RX_L3P/ADC1IN4)
N16999504: C57.1 R90.1 U2.11(DIFFIO_RX_L5N/ADC1IN5)
N16999867: C58.1 R91.1 U2.12(DIFFIO_RX_L5P/ADC1IN6)
N17000151: C59.1 R92.1 U2.13(DIFFIO_RX_L7N/ADC1IN7)
N17000639: C60.1 R93.1 U2.14(DIFFIO_RX_L7P/ADC1IN8)
N17005599: R15.1 R16.1 R94.1
N167529890: D6.1(ANODE) R2.1
N168590211: L3.2 U2.4(REFGND)

Pads without a net: J1 2 3; J2 1 8; J8 32; J9 18 20 31 33; J10 6 7; U1 1 4 9 15 16; U2 21 22 24 25 26 54 78 85 87 122

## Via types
v1: diameter 0.5, hole 0.25, TOP to BOTTOM, 262 vias

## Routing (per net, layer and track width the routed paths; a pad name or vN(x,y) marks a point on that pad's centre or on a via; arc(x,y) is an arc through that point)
3.3V: length 22.5
  TOP w0.28: 37,7.7 37,3.1 36.8,2.9 32,2.9 31.35,3.55 U1.5
  TOP w0.35: 17.6,17.6 17.6,12.5 17.09,11.99 R2.2
  TOP w1.5: 30,20.7 29.95,20.75 J2.4
AGND: length 72.1
  TOP w0.35: v1(27.2,30.6) U3.11 ; C59.2 C58.2 ; C59.2 v1(32,36.4) ; C59.2 C60.2 v1(33.1,36.4) ; C58.2 v1(30.9,36.4) ; C58.2 C57.2 ; R16.3 62.7,15.3 v1(62.7,14.4) ; C57.2 C56.2 ; C57.2 v1(29.8,36.4) ; C56.2 v1(28.7,36.4) ; C56.2 C55.2 ; v1(26.5,36.4) C54.2 ; C54.2 C53.2 v1(25.4,36.4) ; C54.2 C55.2 ; v1(57.6,33.7) R85.2 C24.2 v1(56.5,33.7) ; v1(32.3,27.5) R80.2 C21.2 v1(31.2,27.5) ; v1(46.2,27.5) R83.2 C23.2 v1(47.3,27.5) ; v1(47.3,33.7) C25.2 R82.2 v1(46.2,33.7) ; v1(20.9,33.7) R78.2 C22.2 v1(22,33.7) ; v1(20.9,27.5) R79.2 C19.2 v1(22,27.5) ; v1(31.2,33.7) C20.2 R81.2 v1(32.3,33.7) ; U4.11 v1(52.4,30.6) ; v1(56.5,27.5) C26.2 R84.2 v1(57.6,27.5) ; C55.2 v1(27.6,36.4)
  TOP w0.5: v1(16.4,27.8) 16.4,27.8 C50.2 ; C50.2 v1(15.4,28.8) ; C50.2 16.4,30.4 TP7.1
  BOTTOM w0.35: v1(25.2,48.4) U5.3 ; U5.3 26.89,48.89 C47.1 ; U5.3 27.19,47.61 C61.1 v1(26.4,45.8) 26.3,45.7 C46.1 ; v1(26.1,51) C47.1 ; C47.1 26.9,51.01 v1(26.9,51.8) ; C46.1 R73.1 v1(25.2,45.5) ; C46.1 C12.1 ; v1(40.3,60.2) C49.1 C45.1 v1(40.3,59.1) ; C51.1 27.2,31.39 v1(27.2,30.6) ; v1(40.7,44.8) C5.1 C7.1 v1(41.8,44.8) ; C18.1 30.1,42.89 v1(30.1,42.1) 30.11,42.09 C17.1 ; v1(25.3,39.5) C4.1 C44.1 ; v1(27.6,42.1) 27.6,41.45 L3.1 ; C48.1 24.09,42.29 v1(24.1,42.3) ; C6.1 25.71,59.1 v1(26.5,59.1) ; C52.1 52.41,30.61 v1(52.4,30.6)
DGND: length 62.2
  TOP w0.28: U2.125 23.85,52.25 v1(24.1,52) ; U2.95 31.25,63.25 v1(31.5,63.5) ; U2.133 23.95,48.25 v1(24.1,48.1) ; v1(37,60.9) 37.25,61.15 U2.83 ; v1(31.9,5.6) 31.85,5.65 U1.6 ; v1(24.1,46.2) 24.05,46.25 U2.137 ; U2.68 45.45,58.25 v1(45.5,58.2) ; U2.42 43.15,45.25 42.9,45 v1(42.9,44.5) ; U2.63 42.95,55.75 v1(42.9,55.7) ; C9.1 21.14,43.75 U2.142 ; v1(24.1,56.7) 24.05,56.75 U2.116 ; U2.104 26.75,60.95 v1(26.7,60.9) ; U2.53 42.95,50.75 v1(42.9,50.7)
  TOP w0.35: v1(51.4,4) 51.4,2.32 SW3.3 ; SW1.1 40.4,78.15 v1(40.4,79.4) ; SW2.2 32.7,86.05 v1(32.7,84.8) ; C9.1 21.09,43.7 v1(20.3,43.7) ; v1(20.1,61.1) 20.1,60.31 C14.1 ; SW3.6 59,2.34 v1(59,4) ; v1(46.4,4) 46.4,2.34 SW3.1 ; v1(32.7,79.4) 32.7,78.15 SW2.1 ; SW3.2 48.9,2.3 v1(48.9,4) ; C13.1 22.51,38.29 v1(22.5,38.3) ; v1(16.7,15.9) 15.71,15.9 D6.2 ; v1(53.9,4) 53.9,2.36 SW3.4 ; v1(39.6,29.7) C35.1 ; v1(56.5,4) 56.5,2.3 SW3.5 ; v1(43.6,64.7) 43.6,63.91 C11.1 ; SW1.2 40.4,86.05 v1(40.4,84.8) ; X1.2 42.04,37 v1(43.5,37) ; C15.1 45.91,61.3 v1(46.7,61.3)
  BOTTOM w0.35: R62.1 v1(66.3,83.6) ; v1(24.1,56.7) 23.41,56.7 C10.1 ; C40.1 23.31,46.2 v1(24.1,46.2) ; v1(42.9,44.5) 43.21,44.5 C8.1 ; v1(18.9,56.3) C38.1 C39.1 ; C16.1 43.69,50.7 v1(42.9,50.7) ; v1(24.1,52) 23.31,52 C41.1 ; v1(42.9,47.4) C34.1 C33.1 v1(42.9,48.5) ; v1(40.3,57.6) C27.1 C28.1 v1(40.3,56.5) ; v1(31.5,63.5) C36.1 C37.1 ; C30.1 C29.1 36.99,60.91 v1(37,60.9) ; C31.1 C32.1 v1(37.5,44.1) C43.1 C42.1 v1(37.5,43) C31.1
  vias: v1(21.7,10.1) v1(22.6,10.1) v1(23.2,10.9) v1(23.2,9.3) v1(23.2,8.1) v1(23.2,6.9) v1(27.6,6.1) v1(28.4,6.1) v1(29.8,13.1) v1(29.8,12.1) v1(29.95,8.2) v1(29.95,7.6) v1(29.95,7) v1(31.1,53.9) v1(31.1,52.3) v1(31.1,50.7) v1(31.1,49.1) v1(31.1,8.2) v1(31.1,7.6) v1(31.1,7) v1(32.7,53.9) v1(32.7,52.3) v1(32.7,50.7) v1(32.7,49.1) v1(32.8,13.1) v1(32.8,12.1) v1(34.2,5.9) v1(34.2,4.9) v1(34.2,3.9) v1(34.3,53.9) v1(34.3,52.3) v1(34.3,50.7) v1(34.3,49.1) v1(35.9,53.9) v1(35.9,52.3) v1(35.9,50.7) v1(35.9,49.1)
VBUS_5V:
  vias: v1(27.1,9.3) v1(27.9,9.3) v1(28.7,9.3)
VCC_CORE: length 32.8
  TOP w0.28: U2.115 23.85,57.25 v1(24.1,57.5) ; 24.75,39.69 24.71,39.65 ; 24.75,39.69 U2.1 ; 24.75,39.69 24.75,39.65 ; U2.51 42.95,49.75 v1(42.9,49.7) ; C14.2 21.16,60.25 U2.109 ; v1(44.2,42.1) 43.7,42.1 43.5,42.3 43.5,42.65 43.6,42.75 U2.37 ; C9.2 21.16,42.75 U2.144 ; U2.72 45.86,60.25 C15.2 ; v1(43,40.3) 42.3,40.3 42.25,40.35 U2.36 ; 24.3,62.7 24.7,62.7 24.75,62.65 U2.108
  TOP w0.35: v1(46.7,60.3) 45.91,60.3 C15.2 ; v1(37,29.7) C35.2 37.79,31.95 X1.4 X1.1 v1(42,30.5) ; v1(22.5,39.3) 23.29,39.3 C13.2 24.37,39.31 24.71,39.65 ; v1(42.6,64.7) 42.6,63.91 C11.2 42.25,63.56 U2.73 ; C14.2 21.1,60.31 v1(21.1,61.1) ; v1(23.5,62.7) 24.3,62.7 ; C9.2 21.09,42.7 v1(20.3,42.7)
  BOTTOM w0.35: v1(44.2,42.1) 44.2,42.49 C8.2 ; C10.2 23.41,57.5 v1(24.1,57.5) ; C16.2 43.69,49.7 v1(42.9,49.7)
  vias: v1(40.8,13.2) v1(40.8,12.3) v1(40.8,11.4)
VCC_IO: length 7.3
  BOTTOM w0.35: v1(37,64.7) 36.99,64.69 R26.2 ; R25.2 v1(40.3,55.4) ; v1(24.1,49) 23.41,49 R63.2 ; R47.2 23.41,55.3 v1(24.1,55.3) ; R70.2 v1(37.5,45.2) R27.2 38.3,45.21 v1(38.3,46) ; R38.2 v1(42.9,46.3) ; v1(32.5,60.9) 32.5,60.11 R40.2
  vias: v1(33.2,16) v1(33.2,14.7)
VCC_IO1A: length 60.6
  TOP w0.28: v1(29.1,42.1) 28.75,41.75 U2.9
  BOTTOM w0.35: R6.1 C18.2 29.1,42.89 v1(29.1,42.1) ; v1(29.1,42.1) 29.1,40.7 30.1,39.7 32.3,39.7 33,39 34.1,39 35.1,38 35.1,29.2 35.9,28.4 44.5,28.4 45.5,29.4 62,29.4 66.22,25.18 J8.37 ; v1(29.1,42.1) 29.09,42.09 C17.2
VCC_IO1B: length 109.6
  TOP w0.28: v1(35.7,42.2) 35.75,42.15 U2.23
  TOP w0.35: v1(63.8,34.6) 69.4,29 72.9,29 74.14,30.24 J8.34
  BOTTOM w0.35: 59.9,78.09 R55.2 R56.2 R54.2 ; 59.9,78.09 59.96,78.15 ; 59.9,78.09 59.96,78.03 59.96,78.15 ; 59.9,78.09 62.21,78.09 67.7,72.6 67.7,35.8 66.5,34.6 v1(63.8,34.6) 58.7,39.7 40.41,39.7 37.9,42.2 v1(35.7,42.2) 35.7,42.99 C42.2 C43.2 R70.1 ; 59.96,78.15 J10.4
VCC_IO2: length 38.9
  TOP w0.28: v1(39.6,42.2) 39.75,42.05 U2.31
  TOP w0.35: v1(62.5,41) 67,45.5 J8.21
  BOTTOM w0.35: R27.1 C32.2 C31.2 39.6,42.71 v1(39.6,42.2) 40.4,41.4 43.8,41.4 44.2,41 v1(62.5,41)
VCC_IO3: length 76.2
  TOP w0.28: v1(45.5,44.3) 45.45,44.25 U2.40 ; U2.49 45.45,48.75 v1(45.5,48.7)
  TOP w0.35: J8.1 v1(67,70.9)
  BOTTOM w0.35: v1(45.5,48.7) 44.91,48.7 C33.2 C34.2 R38.1 44.71,45.09 v1(45.5,44.3) 47.7,42.1 63.3,42.1 64.1,41.3 64.1,35.8 64.6,35.3 66.2,35.3 67,36.1 v1(67,70.9)
VCC_IO4: length 47.1
  TOP w0.28: v1(42.9,57.6) 43.05,57.75 U2.67
  TOP w0.35: J8.31 68.8,32.8 v1(65.2,36.4)
  BOTTOM w0.35: v1(65.2,36.4) 65.2,41.9 63.8,43.3 53.71,43.3 53.51,43.5 52.8,43.5 42.11,54.19 R25.1 C28.2 C27.2 v1(42.9,57.6)
VCC_IO5: length 140.9
  TOP w0.28: 37.75,63.15 U2.82 37.75,61.15 v1(38,60.9)
  TOP w0.35: 37.75,63.15 37.75,65.05 42.2,69.5 43.3,69.5 43.9,70.1 v1(43.9,73.1)
  BOTTOM w0.35: v1(43.9,73.1) 42.4,74.6 14.3,74.6 11.9,72.2 11.9,69.6 14.1,67.4 29.7,67.4 33.4,63.7 33.4,59.7 33,59.3 28.5,59.3 27.65,60.15 27.65,61.45 27.02,62.08 25.02,62.08 24,61.05 24,58.6 24.7,57.9 24.7,54.9 24.3,54.5 16.9,54.5 7,44.6 7,30.18 J9.36 ; R26.1 C30.2 C29.2 38.01,60.89 v1(38,60.9)
VCC_IO6: length 42.9
  TOP w0.28: U2.94 31.75,61.15 v1(31.5,60.9) ; 27.3,61.1 27.25,61.15 U2.103 27.25,63.25 v1(27,63.5)
  TOP w0.35: v1(31.5,60.9) 30.8,60.2 27.8,60.2 27.3,60.7 27.3,61.1
  BOTTOM w0.35: R40.1 31.5,60.11 v1(31.5,60.9) C36.2 C37.2 ; J9.1 3.27,69.63 8.27,69.63 18.1,59.8 22,59.8 25.7,63.5 v1(27,63.5)
VCC_IO7: length 33.5
  TOP w0.28: v1(21.5,56.3) 21.55,56.25 U2.117
  BOTTOM w0.35: J9.21 3.3,46.8 6.1,46.8 18.4,59.1 21.6,59.1 22.4,58.3 22.4,57.2 v1(21.5,56.3) C38.2 C39.2 R47.1
VCC_IO8: length 30.5
  TOP w0.28: U2.139 24.05,45.25 v1(24.1,45.2) ; v1(24.1,51) 23.85,50.75 U2.128
  TOP w0.35: R61.1 v1(13.9,11.2) ; R59.1 v1(10.3,11.2) ; R57.1 v1(6.7,11.2) ; v1(19.3,45.7) R52.2 R51.2 v1(19.3,46.8) ; v1(20.1,49.5) R53.2 ; v1(20.1,52.9) 20.1,53.69 R72.1 ; R58.1 v1(8.5,11.2) ; R60.1 v1(12.1,11.2)
  BOTTOM w0.35: R68.1 v1(48.9,6.6) ; v1(24.1,45.2) 23.31,45.2 C40.2 ; R66.1 v1(53.9,6.6) ; R65.1 v1(56.5,6.6) ; R64.1 v1(59,6.6) ; v1(24.1,51) 23.31,51 C41.2 R63.1 ; R69.1 v1(46.4,6.6) ; R67.1 v1(51.4,6.6)
  BOTTOM w1: v1(11.2,38.9) v1(11.2,39.7) v1(11.2,40.5) 14.1,43.4 17.6,43.4 19.5,45.3 19.7,45.3
VCCA_3.3V: length 33.6
  TOP w0.28: U2.107 25.25,61.15 v1(25.5,60.9) ; v1(24.1,43.3) 24.05,43.25 U2.143 ; U2.71 43.05,59.75 v1(42.9,59.9) ; v1(40.9,42.2) 41.25,41.85 U2.34 ; v1(25.2,42.1) 25.25,42.05 U2.2 ; U2.35 41.75,42.15 v1(41.8,42.2)
  TOP w0.35: U4.4 v1(51.4,30.6) ; v1(26.2,30.6) U3.4 ; R15.2 v1(62.6,16.7)
  TOP w0.5: L2.2 16.7,26.6 v1(16.7,26.6) ; L2.2 17.8,26.6 v1(18.8,26.6) ; L2.2 v1(17.8,27.7) 17.8,27.7 C50.1 17.8,31.2 TP6.1
  BOTTOM w0.35: v1(40.9,42.2) 40.7,42.4 C5.2 ; v1(25.2,42.1) 25.2,41.41 C4.2 C44.2 ; U5.1 27.91,50.04 C47.2 ; v1(28.7,51) C47.2 ; C47.2 27.9,51.01 v1(27.9,51.8) ; v1(24.1,43.3) 23.11,43.3 C48.2 ; v1(26.2,30.6) 26.2,31.39 C51.2 ; C6.2 25.7,60.7 v1(25.5,60.9) ; R6.2 30.1,44.01 v1(30.1,44.8) ; v1(51.4,30.6) 51.39,30.61 C52.2 ; C45.2 C49.2 42.6,60.2 v1(42.9,59.9) ; C7.2 v1(41.8,42.2)
ADC1IN1: length 4.7
  TOP w0.16: 22.6,34.41 22.18,34.41 R86.1 ; 22.6,34.41 22.6,33.3 22.76,33.14 U3.2 ; 22.6,34.41 U3.1
ADC1IN2: length 4.6
  TOP w0.16: 22.6,26.79 22.1,26.79 R87.1 ; 22.6,26.79 22.6,27.9 22.76,28.06 U3.6 ; 22.6,26.79 U3.7
ADC1IN3: length 4.6
  TOP w0.16: 30.6,26.79 31.1,26.79 R88.1 ; 30.6,26.79 30.6,27.9 30.44,28.06 U3.9 ; 30.6,26.79 U3.8
ADC1IN4: length 4.6
  TOP w0.16: 30.6,34.41 30.6,33.3 30.44,33.14 U3.13 ; 30.6,34.41 U3.14 ; 30.6,34.41 31.1,34.41 R89.1
ADC1IN5: length 4.6
  TOP w0.16: 47.9,34.41 47.9,33.3 48.06,33.14 U4.2 ; 47.9,34.41 47.4,34.41 R90.2 ; 47.9,34.41 U4.1
ADC1IN6: length 4.6
  TOP w0.16: 47.9,26.79 47.9,27.9 48.06,28.06 U4.6 ; 47.9,26.79 U4.7 ; 47.9,26.79 47.4,26.79 R91.2
ADC1IN7: length 4.6
  TOP w0.16: 55.9,26.79 55.9,27.9 55.74,28.06 U4.9 ; 55.9,26.79 56.4,26.79 R92.2 ; 55.9,26.79 U4.8
ADC1IN8: length 4.6
  TOP w0.16: U4.14 55.9,34.41 ; 55.9,34.41 55.9,33.3 55.74,33.14 U4.13 ; 55.9,34.41 56.4,34.41 R93.2
ARDUINO_A0: length 34.9
  TOP w0.16: R10.2 19.21,32.91 19,32.7 19,27.8 19.4,27.4 19.4,26 20.5,24.9 42.93,24.9 J4.1
ARDUINO_A1: length 31.5
  TOP w0.16: R8.2 19.8,26.2 20.7,25.3 43.2,25.3 44.7,23.8 46.57,23.8 J4.2
ARDUINO_A2: length 19.2
  TOP w0.16: J4.3 48.71,24.2 45,24.2 41.8,27.4 34.29,27.4 R7.2
ARDUINO_A3: length 25.5
  TOP w0.16: J4.4 50.85,24.6 45.3,24.6 42,27.9 36,27.9 34.4,29.5 34.4,32.6 34.1,32.9 33.41,32.9 R9.2
ARDUINO_A4: length 19.7
  TOP w0.16: R20.2 44.61,32.91 44.4,32.7 44.4,26.2 45.6,25 52.99,25 J4.5
ARDUINO_A5: length 16.5
  TOP w0.16: J4.6 55.13,25.4 45.9,25.4 44.9,26.4 44.9,28.1 45.09,28.29 R18.2
ARDUINO_A6: length 11.6
  BOTTOM w0.16: J4.7 60.43,19.73 59.3,18.6 55.4,18.6 54.5,17.7 J7.1
ARDUINO_A7: length 24.5
  BOTTOM w0.16: J4.8 61.7,21.37 61.7,15.5 60.7,14.5 47.1,14.5 J6.1
ARDUINO_IO0: length 21.2
  TOP w0.16: U2.74 41.75,64.65 43.6,66.5 53.49,66.5 J5.8
ARDUINO_IO1: length 19.2
  TOP w0.16: J5.7 51.35,66.9 43.4,66.9 41.25,64.75 U2.75
ARDUINO_IO2: length 17.2
  TOP w0.16: U2.76 40.75,64.85 43.2,67.3 49.21,67.3 J5.6
ARDUINO_IO3: length 15.2
  TOP w0.16: U2.77 40.25,64.95 43,67.7 47.07,67.7 J5.5
ARDUINO_IO4: length 14.3
  TOP w0.16: J5.4 47.73,69.43 46.4,68.1 42.8,68.1 39.25,64.55 U2.79
ARDUINO_IO5: length 12.9
  TOP w0.16: J5.3 45.19,69.39 44.7,68.9 42.4,68.9 38.25,64.75 U2.81
ARDUINO_IO6: length 11.5
  TOP w0.16: U2.84 36.75,63.15 36.5,63.4 36.5,65 42.4,70.9 J5.2
ARDUINO_IO7: length 10.5
  TOP w0.16: J5.1 36.1,66.89 36.1,63.5 35.75,63.15 U2.86
ARDUINO_IO8: length 21.2
  TOP w0.16: U2.62 45.45,55.25 v1(45.5,55.3)
  BOTTOM w0.16: v1(45.5,55.3) 44.9,55.3 43.7,56.5 43.7,60.9 36.05,68.55 J3.8
ARDUINO_IO9: length 26.1
  TOP w0.16: v1(46.1,56.1) 45.3,56.1 45.15,56.25 U2.64
  BOTTOM w0.16: v1(46.1,56.1) 45.1,56.1 44.1,57.1 44.1,61.1 37.3,67.9 37.3,71.4 36.6,72.1 34.71,72.1 J3.7
ARDUINO_IO10: length 27.2
  TOP w0.16: U2.65 45.45,56.75 v1(45.5,56.7)
  BOTTOM w0.16: v1(45.5,56.7) 44.5,57.7 44.5,61.3 37.7,68.1 37.7,71.6 36.8,72.5 32.57,72.5 J3.6
ARDUINO_IO11: length 53.9
  TOP w0.16: U2.66 46.05,57.25 v1(46.1,57.3)
  BOTTOM w0.16: J11.4 59.32,46.8 56.5,46.8 54.8,48.5 54.8,54.6 52.1,57.3 v1(46.1,57.3) 45.5,57.3 44.9,57.9 44.9,61.5 38.1,68.3 38.1,71.8 37,72.9 30.43,72.9 J3.5
ARDUINO_IO12: length 51
  TOP w0.16: v1(46.1,58.8) 46.05,58.75 U2.69
  BOTTOM w0.16: J3.4 28.29,73.3 37.2,73.3 38.5,72 38.5,69.3 40.1,67.7 41.3,67.7 45.4,63.6 45.4,59.5 v1(46.1,58.8) 54.1,58.8 58,54.9 58,50.6 J11.1
ARDUINO_IO13: length 58.5
  TOP w0.16: U2.70 45.45,59.25 45.6,59.4 v1(46.7,59.4)
  BOTTOM w0.16: J3.3 26.15,73.7 37.4,73.7 38.9,72.2 38.9,69.6 40.3,68.2 41.5,68.2 45.9,63.8 45.9,60.2 v1(46.7,59.4) 54.9,59.4 59.3,55 59.3,49.32 J11.3
ARDUINO_VREF: length 44.2
  BOTTOM w0.35: R74.1 30.31,46.79 29.9,47.2 29.9,55.3 31.4,56.8 34,56.8 35.5,58.3 35.5,67.3 33.4,69.4 19.8,69.4 18.3,70.9 J3.1
BOOT_SEL: length 97.1
  TOP w0.16: SW3.7 59,10.86 v1(59,9.2) ; U2.126 21.4,51.75 20.95,51.3 18.8,51.3 v1(16.7,49.2)
  BOTTOM w0.16: v1(16.7,49.2) 16.7,46.2 16.3,45.8 14.2,45.8 9.9,41.5 9.9,23.6 13,20.5 41.3,20.5 43.8,18 43.8,13.4 45.4,11.8 56.4,11.8 v1(59,9.2) R64.2
DIFFIO_B1N: length 39.2
  TOP w0.13: U2.38 44.95,43.25 45.07,43.37 46.08,43.37 46.21,43.24 46.21,41.98 46.49,41.7 46.97,41.7 47.25,41.98 47.25,43.24 47.38,43.37 48.76,43.37 50.56,41.57 53.33,41.57 53.9,41 R30.1 54.1,41 54.67,41.57 61.27,41.57 66.34,46.64 72.38,46.64 73,47.26 73,48.79 73.39,49.18 74.01,49.18 74.14,49.05 J8.20
DIFFIO_B1P: length 39.2
  TOP w0.13: U2.39 44.95,43.75 45.07,43.63 46.19,43.63 46.47,43.35 46.47,42.09 46.6,41.96 46.86,41.96 46.99,42.09 46.99,43.35 47.27,43.63 48.87,43.63 50.67,41.83 53.33,41.83 53.9,42.4 R30.2 54.1,42.4 54.67,41.83 61.16,41.83 66.23,46.9 72.27,46.9 72.74,47.37 72.74,48.9 73.28,49.44 74.01,49.44 74.14,49.57 J8.18
DIFFIO_B3N: length 39.4
  TOP w0.13: J8.19 71.6,49.05 71.47,49.18 70.02,49.18 68.8,50.4 68.26,50.4 68.13,50.27 68.13,49.58 67.85,49.3 67.37,49.3 67.09,49.58 67.09,50.27 66.96,50.4 66.7,50.4 66.57,50.27 66.57,49.58 66.29,49.3 65.81,49.3 65.53,49.58 65.53,50.27 65.4,50.4 63.9,50.4 63.1,49.6 63.1,44.9 61.57,43.37 52.77,43.37 52.2,42.8 R33.1 52,42.8 51.43,43.37 50.76,43.37 49.01,45.12 45.33,45.12 45.09,44.88 45.09,44.88 44.95,44.75 U2.41
DIFFIO_B3P: length 39.4
  TOP w0.13: U2.43 44.95,45.75 45.09,45.62 45.09,45.62 45.33,45.38 49.12,45.38 50.87,43.63 51.43,43.63 52,44.2 R33.2 52.2,44.2 52.77,43.63 61.46,43.63 62.84,45.01 62.84,49.71 63.79,50.66 65.51,50.66 65.79,50.38 65.79,49.69 65.92,49.56 66.18,49.56 66.31,49.69 66.31,50.38 66.59,50.66 67.07,50.66 67.35,50.38 67.35,49.69 67.48,49.56 67.74,49.56 67.87,49.69 67.87,50.38 68.15,50.66 68.91,50.66 70.13,49.44 71.47,49.44 71.6,49.57 J8.17
DIFFIO_B5N: length 39.5
  TOP w0.13: U2.44 44.95,46.25 45.07,46.37 50.14,46.37 52.7,48.93 52.7,53.1 52.97,53.37 53.43,53.37 54,52.8 R36.1 54.2,52.8 54.77,53.37 61.46,53.37 63.11,51.72 72.38,51.72 73,52.34 73,53.87 73.39,54.26 74.01,54.26 74.14,54.13 J8.16
DIFFIO_B5P: length 39.5
  TOP w0.13: U2.45 44.95,46.75 45.07,46.63 50.03,46.63 52.44,49.04 52.44,53.24 52.83,53.63 53.43,53.63 54,54.2 R36.2 54.2,54.2 54.77,53.63 61.57,53.63 63.22,51.98 72.27,51.98 72.74,52.45 72.74,53.98 73.28,54.52 73.97,54.52 74.14,54.69 J8.14
DIFFIO_B7N: length 40.2
  TOP w0.13: U2.46 44.95,47.25 45.07,47.37 48.54,47.37 51.7,50.53 51.7,54.53 52.74,55.57 55.33,55.57 55.9,55 R29.1 56.1,55 56.67,55.57 62.72,55.57 64.03,54.26 66.61,54.26 66.9,54.54 66.9,55.11 67.03,55.24 67.29,55.24 67.42,55.11 67.42,53.56 67.7,53.28 68.17,53.28 68.46,53.56 68.46,55.11 68.59,55.24 68.85,55.24 68.98,55.11 68.98,54.54 69.26,54.26 71.47,54.26 71.6,54.13 J8.15
DIFFIO_B7P: length 40.2
  TOP w0.13: U2.47 44.95,47.75 45.07,47.63 48.43,47.63 51.44,50.64 51.44,54.64 52.63,55.83 55.33,55.83 55.9,56.4 R29.2 56.1,56.4 56.67,55.83 62.83,55.83 64.14,54.52 66.51,54.52 66.64,54.65 66.64,55.22 66.92,55.5 67.39,55.5 67.68,55.22 67.68,53.67 67.81,53.54 68.07,53.54 68.2,53.67 68.2,55.22 68.48,55.5 68.95,55.5 69.24,55.22 69.24,54.65 69.37,54.52 71.47,54.52 71.6,54.65 J8.13
DIFFIO_B9N: length 39.5
  TOP w0.13: J8.12 74.14,59.21 74.01,59.34 73.39,59.34 73,58.95 73,57.42 72.38,56.8 64.03,56.8 63.06,57.77 54.77,57.77 54.2,57.2 R32.1 54,57.2 53.43,57.77 52.44,57.77 50.8,56.13 50.8,52.5 47.92,49.62 45.33,49.62 45.09,49.38 45.09,49.38 44.95,49.25 U2.50
DIFFIO_B9P: length 39.5
  TOP w0.13: U2.52 44.95,50.25 45.09,50.12 45.09,50.12 45.33,49.88 47.81,49.88 50.54,52.61 50.54,56.24 52.33,58.03 53.43,58.03 54,58.6 R32.2 54.2,58.6 54.77,58.03 63.17,58.03 64.14,57.06 72.27,57.06 72.74,57.53 72.74,59.06 73.28,59.6 74.01,59.6 74.14,59.73 J8.10
DIFFIO_B12N: length 39.4
  TOP w0.13: U2.55 44.95,51.75 45.07,51.87 48.27,51.87 49.9,53.5 49.9,58.63 51.24,59.97 55.33,59.97 55.9,59.4 R35.1 56.1,59.4 56.67,59.97 64.33,59.97 64.96,59.34 66.78,59.34 67.06,59.62 67.06,60.01 67.19,60.14 67.45,60.14 67.58,60.01 67.58,58.82 67.86,58.54 68.34,58.54 68.62,58.82 68.62,60.01 68.75,60.14 69.01,60.14 69.14,60.01 69.14,59.62 69.42,59.34 71.47,59.34 71.6,59.21 J8.11
DIFFIO_B12P: length 39.4
  TOP w0.13: J8.9 71.6,59.73 71.47,59.6 69.53,59.6 69.4,59.73 69.4,60.12 69.12,60.4 68.64,60.4 68.36,60.12 68.36,58.93 68.23,58.8 67.97,58.8 67.84,58.93 67.84,60.12 67.56,60.4 67.08,60.4 66.8,60.12 66.8,59.73 66.67,59.6 65.07,59.6 64.44,60.23 56.67,60.23 56.1,60.8 R35.2 55.9,60.8 55.33,60.23 51.13,60.23 49.64,58.74 49.64,53.61 48.16,52.13 45.07,52.13 44.95,52.25 U2.56
DIFFIO_B14N: length 40.7
  TOP w0.13: J8.8 74.14,64.29 74.01,64.42 73.39,64.42 73,64.03 73,62.5 72.38,61.88 66.72,61.88 66.43,62.17 54.77,62.17 54.2,61.6 R37.1 54,61.6 53.43,62.17 51.14,62.17 49,60.03 49,54.4 47.47,52.87 45.07,52.87 44.95,52.75 U2.57
DIFFIO_B14P: length 40.7
  TOP w0.13: U2.58 44.95,53.25 45.07,53.13 47.36,53.13 48.74,54.51 48.74,60.14 51.03,62.43 53.43,62.43 54,63 R37.2 54.2,63 54.77,62.43 66.54,62.43 66.83,62.14 72.27,62.14 72.74,62.61 72.74,64.14 73.28,64.68 74.01,64.68 74.14,64.81 J8.6
DIFFIO_B16N: length 39.3
  TOP w0.13: J8.7 71.6,64.29 71.47,64.42 69.01,64.42 67.39,66.04 60.71,66.04 59.09,64.42 56.72,64.42 56.1,63.8 R39.1 55.9,63.8 55.33,64.37 49.67,64.37 48.1,62.8 48.1,55 46.97,53.87 45.07,53.87 44.95,53.75 U2.59
DIFFIO_B16P: length 39.2
  TOP w0.13: J8.5 71.6,64.81 71.47,64.68 69.12,64.68 67.5,66.3 60.6,66.3 58.98,64.68 56.62,64.68 56.1,65.2 R39.2 55.9,65.2 55.33,64.63 49.56,64.63 47.84,62.91 47.84,55.11 46.86,54.13 45.07,54.13 44.95,54.25 U2.60
DIFFIO_L20N/CLK1N: length 41.6
  TOP w0.13: U2.28 38.25,40.05 38.37,39.93 38.37,39.53 39.4,38.5 49.93,38.5 50.46,37.97 53.33,37.97 53.9,37.4 R31.1 54.1,37.4 54.67,37.97 68.33,37.97 69.82,36.48 72.28,36.48 73,37.2 73,38.43 73.59,39.02 73.93,39.02 74.14,38.81 J8.28
DIFFIO_L20P/CLK1P: length 41.6
  TOP w0.13: U2.29 38.75,40.05 38.63,39.93 38.63,39.64 39.51,38.76 50.04,38.76 50.57,38.23 53.33,38.23 53.9,38.8 R31.2 54.1,38.8 54.67,38.23 68.44,38.23 69.93,36.74 72.17,36.74 72.74,37.31 72.74,38.54 73.48,39.28 74.28,39.28 74.4,39.4 74.4,40.16 J8.26
DIFFIO_L27N/PLL_CLKOUTN: length 40
  TOP w0.13: U2.32 40.25,40.05 40.37,39.93 40.37,39.58 40.65,39.3 49.07,39.3 49.54,39.77 51.43,39.77 52,39.2 R34.1 52.2,39.2 52.77,39.77 66.39,39.77 66.67,40.05 66.67,41.21 66.8,41.34 67.06,41.34 67.19,41.21 67.19,40.05 67.47,39.77 67.95,39.77 68.23,40.05 68.23,41.21 68.36,41.34 68.62,41.34 68.75,41.21 68.75,39.78 69.51,39.02 71.33,39.02 71.6,38.75 J8.27
DIFFIO_L27P/PLL_CLKOUTP: length 40
  TOP w0.13: U2.33 40.75,40.05 40.63,39.93 40.63,39.69 40.76,39.56 48.96,39.56 49.43,40.03 51.43,40.03 52,40.6 R34.2 52.2,40.6 52.77,40.03 66.28,40.03 66.41,40.16 66.41,41.32 66.69,41.6 67.17,41.6 67.45,41.32 67.45,40.16 67.58,40.03 67.84,40.03 67.97,40.16 67.97,41.32 68.25,41.6 68.73,41.6 69.01,41.32 69.01,39.89 69.62,39.28 71.68,39.28 71.85,39.45 71.85,40.17 J8.25
DIFFIO_R14N/CLK2N: length 41.4
  TOP w0.13: J9.7 1.8,63.48 1.8,64.3 1.92,64.42 2.69,64.42 3.4,65.13 3.4,66.33 4.04,66.97 12.43,66.97 13,66.4 R41.2 13.2,66.4 13.77,66.97 16.24,66.97 17.51,68.24 32.29,68.24 34.37,66.16 34.37,63.07 34.25,62.95 U2.89
DIFFIO_R14P/CLK2P: length 41.4
  TOP w0.13: U2.88 34.75,62.95 34.63,63.07 34.63,66.27 32.4,68.5 17.4,68.5 16.13,67.23 13.77,67.23 13.2,67.8 R41.1 13,67.8 12.43,67.23 3.93,67.23 3.14,66.44 3.14,65.24 2.58,64.68 2.32,64.68 2,65 J9.5
DIFFIO_R16N/CLK3N: length 40.5
  TOP w0.13: U2.91 33.25,62.95 33.37,63.07 33.37,65.66 31.59,67.44 18.71,67.44 16.44,65.17 15.67,65.17 15.1,64.6 R43.2 14.9,64.6 14.33,65.17 11.57,65.17 11.29,65.45 11.29,65.91 11.16,66.04 10.9,66.04 10.77,65.91 10.77,64.58 10.49,64.3 10.01,64.3 9.73,64.58 9.73,65.91 9.6,66.04 9.34,66.04 9.21,65.91 9.21,65.45 8.93,65.17 7,65.17 6.25,64.42 4.42,64.42 4.3,64.3 4.3,63.52 J9.8
DIFFIO_R16P/CLK3P: length 40.5
  TOP w0.13: U2.90 33.75,62.95 33.63,63.07 33.63,65.77 31.7,67.7 18.6,67.7 16.33,65.43 15.67,65.43 15.1,66 R43.1 14.9,66 14.33,65.43 11.68,65.43 11.55,65.56 11.55,66.02 11.27,66.3 10.79,66.3 10.51,66.02 10.51,64.69 10.38,64.56 10.12,64.56 9.99,64.69 9.99,66.02 9.71,66.3 9.23,66.3 8.95,66.02 8.95,65.56 8.82,65.43 6.89,65.43 6.14,64.68 4.82,64.68 4.54,64.96 J9.6
DIFFIO_R18N: length 39.5
  TOP w0.13: J9.11 1.8,58.4 1.8,59.2 1.94,59.34 2.89,59.34 3.4,59.85 3.4,61.45 3.83,61.88 5.98,61.88 7.47,63.37 12.43,63.37 13,62.8 R45.2 13.2,62.8 13.77,63.37 15.94,63.37 19.21,66.64 30.49,66.64 32.37,64.76 32.37,63.07 32.25,62.95 U2.93
DIFFIO_R18P: length 39.6
  TOP w0.13: J9.9 2,59.9 2.3,59.6 2.78,59.6 3.14,59.96 3.14,61.56 3.72,62.14 5.87,62.14 7.36,63.63 12.43,63.63 13,64.2 R45.1 13.2,64.2 13.77,63.63 15.83,63.63 19.1,66.9 30.6,66.9 32.63,64.87 32.63,63.07 32.75,62.95 U2.92
DIFFIO_R26N/DPCLK2: length 39.4
  TOP w0.13: U2.98 29.75,62.95 29.89,63.09 29.89,63.09 30.12,63.33 30.12,63.89 30.7,64.47 30.7,65.03 29.89,65.84 19.74,65.84 16.5,62.6 16.5,62 16.07,61.57 15.67,61.57 15.1,61 R46.2 14.9,61 14.33,61.57 11.94,61.57 11.66,61.85 11.66,62.31 11.53,62.44 11.27,62.44 11.14,62.31 11.14,60.98 10.85,60.7 10.38,60.7 10.1,60.98 10.1,62.24 9.89,62.44 9.51,62.44 9.32,62.25 9.32,60.85 7.81,59.34 4.44,59.34 4.3,59.2 4.3,58.44 J9.12
DIFFIO_R26P/DPCLK3: length 39.4
  TOP w0.13: U2.96 30.75,62.95 30.61,63.09 30.61,63.09 30.38,63.33 30.38,63.78 30.96,64.36 30.96,65.14 30,66.1 19.63,66.1 16.24,62.71 16.24,62.11 15.96,61.83 15.67,61.83 15.1,62.4 R46.1 14.9,62.4 14.33,61.83 12.05,61.83 11.92,61.96 11.92,62.42 11.63,62.7 11.16,62.7 10.88,62.42 10.88,61.09 10.75,60.96 10.49,60.96 10.36,61.09 10.36,62.34 10,62.7 9.4,62.7 9.06,62.36 9.06,60.96 7.7,59.6 4.8,59.6 4.54,59.86 J9.10
DIFFIO_R27N: length 40.7
  TOP w0.13: J9.15 1.8,53.32 1.8,54.16 1.9,54.26 2.89,54.26 3.4,54.77 3.4,56.37 3.83,56.8 6.77,56.8 9.74,59.77 12.43,59.77 13,59.2 R48.2 13.2,59.2 13.77,59.77 16.24,59.77 17.26,60.79 17.26,62.06 20.24,65.04 28.39,65.04 29.12,64.31 29.12,63.82 v1(28.9,63.6) ; v1(28.4,60.9) 28.25,61.05 U2.101
  BOTTOM w0.13: v1(28.4,60.9) 28.62,61.12 28.62,61.99 29.12,62.49 29.12,63.38 v1(28.9,63.6)
DIFFIO_R27P: length 40.7
  TOP w0.13: J9.13 2,54.8 2.28,54.52 2.78,54.52 3.14,54.88 3.14,56.48 3.72,57.06 6.66,57.06 9.63,60.03 12.43,60.03 13,60.6 R48.1 13.2,60.6 13.77,60.03 16.13,60.03 17,60.9 17,62.17 20.13,65.3 28.5,65.3 29.38,64.42 29.38,63.82 v1(29.6,63.6) ; v1(29.1,60.9) 29.25,61.05 U2.99
  BOTTOM w0.13: v1(29.6,63.6) 29.38,63.38 29.38,62.38 28.88,61.88 28.88,61.12 v1(29.1,60.9)
DIFFIO_R28N: length 39.4
  TOP w0.13: U2.102 27.75,62.95 27.89,63.09 27.89,63.09 28.12,63.33 28.12,63.88 27.76,64.24 20.74,64.24 18.06,61.56 18.06,59.69 16.34,57.97 15.67,57.97 15.1,57.4 R49.2 14.9,57.4 14.33,57.97 9.84,57.97 8.3,56.43 8.3,51.53 8.01,51.24 6.96,51.24 6.6,51.6 6.6,54 6.34,54.26 4.46,54.26 4.3,54.1 4.3,53.36 J9.16
DIFFIO_R28P: length 39.4
  TOP w0.13: U2.100 28.75,62.95 28.61,63.09 28.61,63.09 28.38,63.33 28.38,63.99 27.87,64.5 20.63,64.5 17.8,61.67 17.8,59.8 16.23,58.23 15.67,58.23 15.1,58.8 R49.1 14.9,58.8 14.33,58.23 9.73,58.23 8.04,56.54 8.04,51.64 7.9,51.5 7.07,51.5 6.86,51.71 6.86,54.11 6.45,54.52 4.88,54.52 4.54,54.86 J9.14
DIFFIO_R33N: length 40.6
  TOP w0.13: J9.19 1.8,48.24 1.8,49.08 1.9,49.18 5.79,49.18 6.24,48.73 6.24,47.86 6.9,47.2 8.8,47.2 9.46,47.86 9.46,55.36 10.27,56.17 12.43,56.17 13,55.6 R50.2 13.2,55.6 13.77,56.17 16.14,56.17 19.16,59.19 19.16,61.29 21.31,63.44 25.69,63.44 25.87,63.26 25.87,63.07 25.75,62.95 U2.106
DIFFIO_R33P: length 40.6
  TOP w0.13: J9.17 2,49.8 2.36,49.44 5.9,49.44 6.5,48.84 6.5,47.97 7.01,47.46 8.69,47.46 9.2,47.97 9.2,55.47 10.16,56.43 12.43,56.43 13,57 R50.1 13.2,57 13.77,56.43 16.03,56.43 18.9,59.3 18.9,61.4 21.2,63.7 25.8,63.7 26.13,63.37 26.13,63.07 26.25,62.95 U2.105
DIFFIO_T1N: length 39.2
  TOP w0.13: U2.111 22.05,59.25 21.93,59.37 20.64,59.37 19.7,58.43 19.7,58 16.07,54.37 15.67,54.37 15.1,53.8 R42.2 14.9,53.8 14.33,54.37 11.14,54.37 10.56,53.79 10.56,42.16 9.5,41.1 6.66,41.1 6.2,41.56 3.83,41.56 3.4,41.13 3.4,39.53 2.89,39.02 2.13,39.02 2,38.89 J9.27
DIFFIO_T1P: length 39.2
  TOP w0.13: U2.110 22.05,59.75 21.93,59.63 20.53,59.63 19.44,58.54 19.44,58.11 15.96,54.63 15.67,54.63 15.1,55.2 R42.1 14.9,55.2 14.33,54.63 11.03,54.63 10.3,53.9 10.3,42.27 9.39,41.36 6.77,41.36 6.31,41.82 3.72,41.82 3.14,41.24 3.14,39.64 2.78,39.28 2.13,39.28 2,39.41 J9.25
DIFFIO_T4N: length 35.2
  TOP w0.16: v1(20.7,57.5) 21.45,58.25 U2.113
  BOTTOM w0.16: J9.32 6.1,34.36 6.1,45.2 18.4,57.5 v1(20.7,57.5)
DIFFIO_T6P: length 37.1
  TOP w0.16: v1(21.5,57.5) 21.75,57.75 U2.114
  BOTTOM w0.16: J9.34 6.5,32.22 6.5,44.9 18.5,56.9 20.9,56.9 v1(21.5,57.5)
DIFFIO_T10N: length 39.2
  TOP w0.13: J9.28 4.54,38.89 4.67,39.02 6.41,39.02 8.99,36.44 11.91,36.44 12.9,37.43 12.9,49.37 11.66,50.61 11.66,52.29 11.94,52.57 12.43,52.57 13,52 R44.2 13.2,52 13.77,52.57 15.87,52.57 18.67,55.37 21.93,55.37 22.05,55.25 U2.119
DIFFIO_T10P: length 39.2
  TOP w0.13: J9.26 4.54,39.41 4.67,39.28 6.52,39.28 9.1,36.7 11.8,36.7 12.64,37.54 12.64,49.26 11.4,50.5 11.4,52.4 11.83,52.83 12.43,52.83 13,53.4 R44.1 13.2,53.4 13.77,52.83 15.76,52.83 18.56,55.63 21.93,55.63 22.05,55.75 U2.118
JTAGEN: length 107.6
  TOP w0.16: U2.15 31.75,41.75 31.5,42 v1(31.5,42.7) ; v1(69.8,75.6) 57.7,75.6 54.88,78.42 J10.8
  BOTTOM w0.16: J10.8 54.9,81.04 R56.1 ; v1(69.8,75.6) 69.8,34.7 67.5,32.4 62.8,32.4 57.2,38 39.4,38 37.2,40.2 33.2,40.2 31.5,41.9 v1(31.5,42.7)
